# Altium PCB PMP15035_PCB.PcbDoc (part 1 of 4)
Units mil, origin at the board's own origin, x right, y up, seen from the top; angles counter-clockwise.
Board outline 5645 x 4585 mil, 8 copper layers (Top Layer, Signal Layer 1, Signal Layer 2, Signal Layer 3, Signal Layer 4, Signal Layer 5, Signal Layer 6, Bottom Layer), stack 60.9 mil thick; 335 components, 164 nets, 981 pads, 1349 vias.
Unrouted connection lines stored in the file: 46.
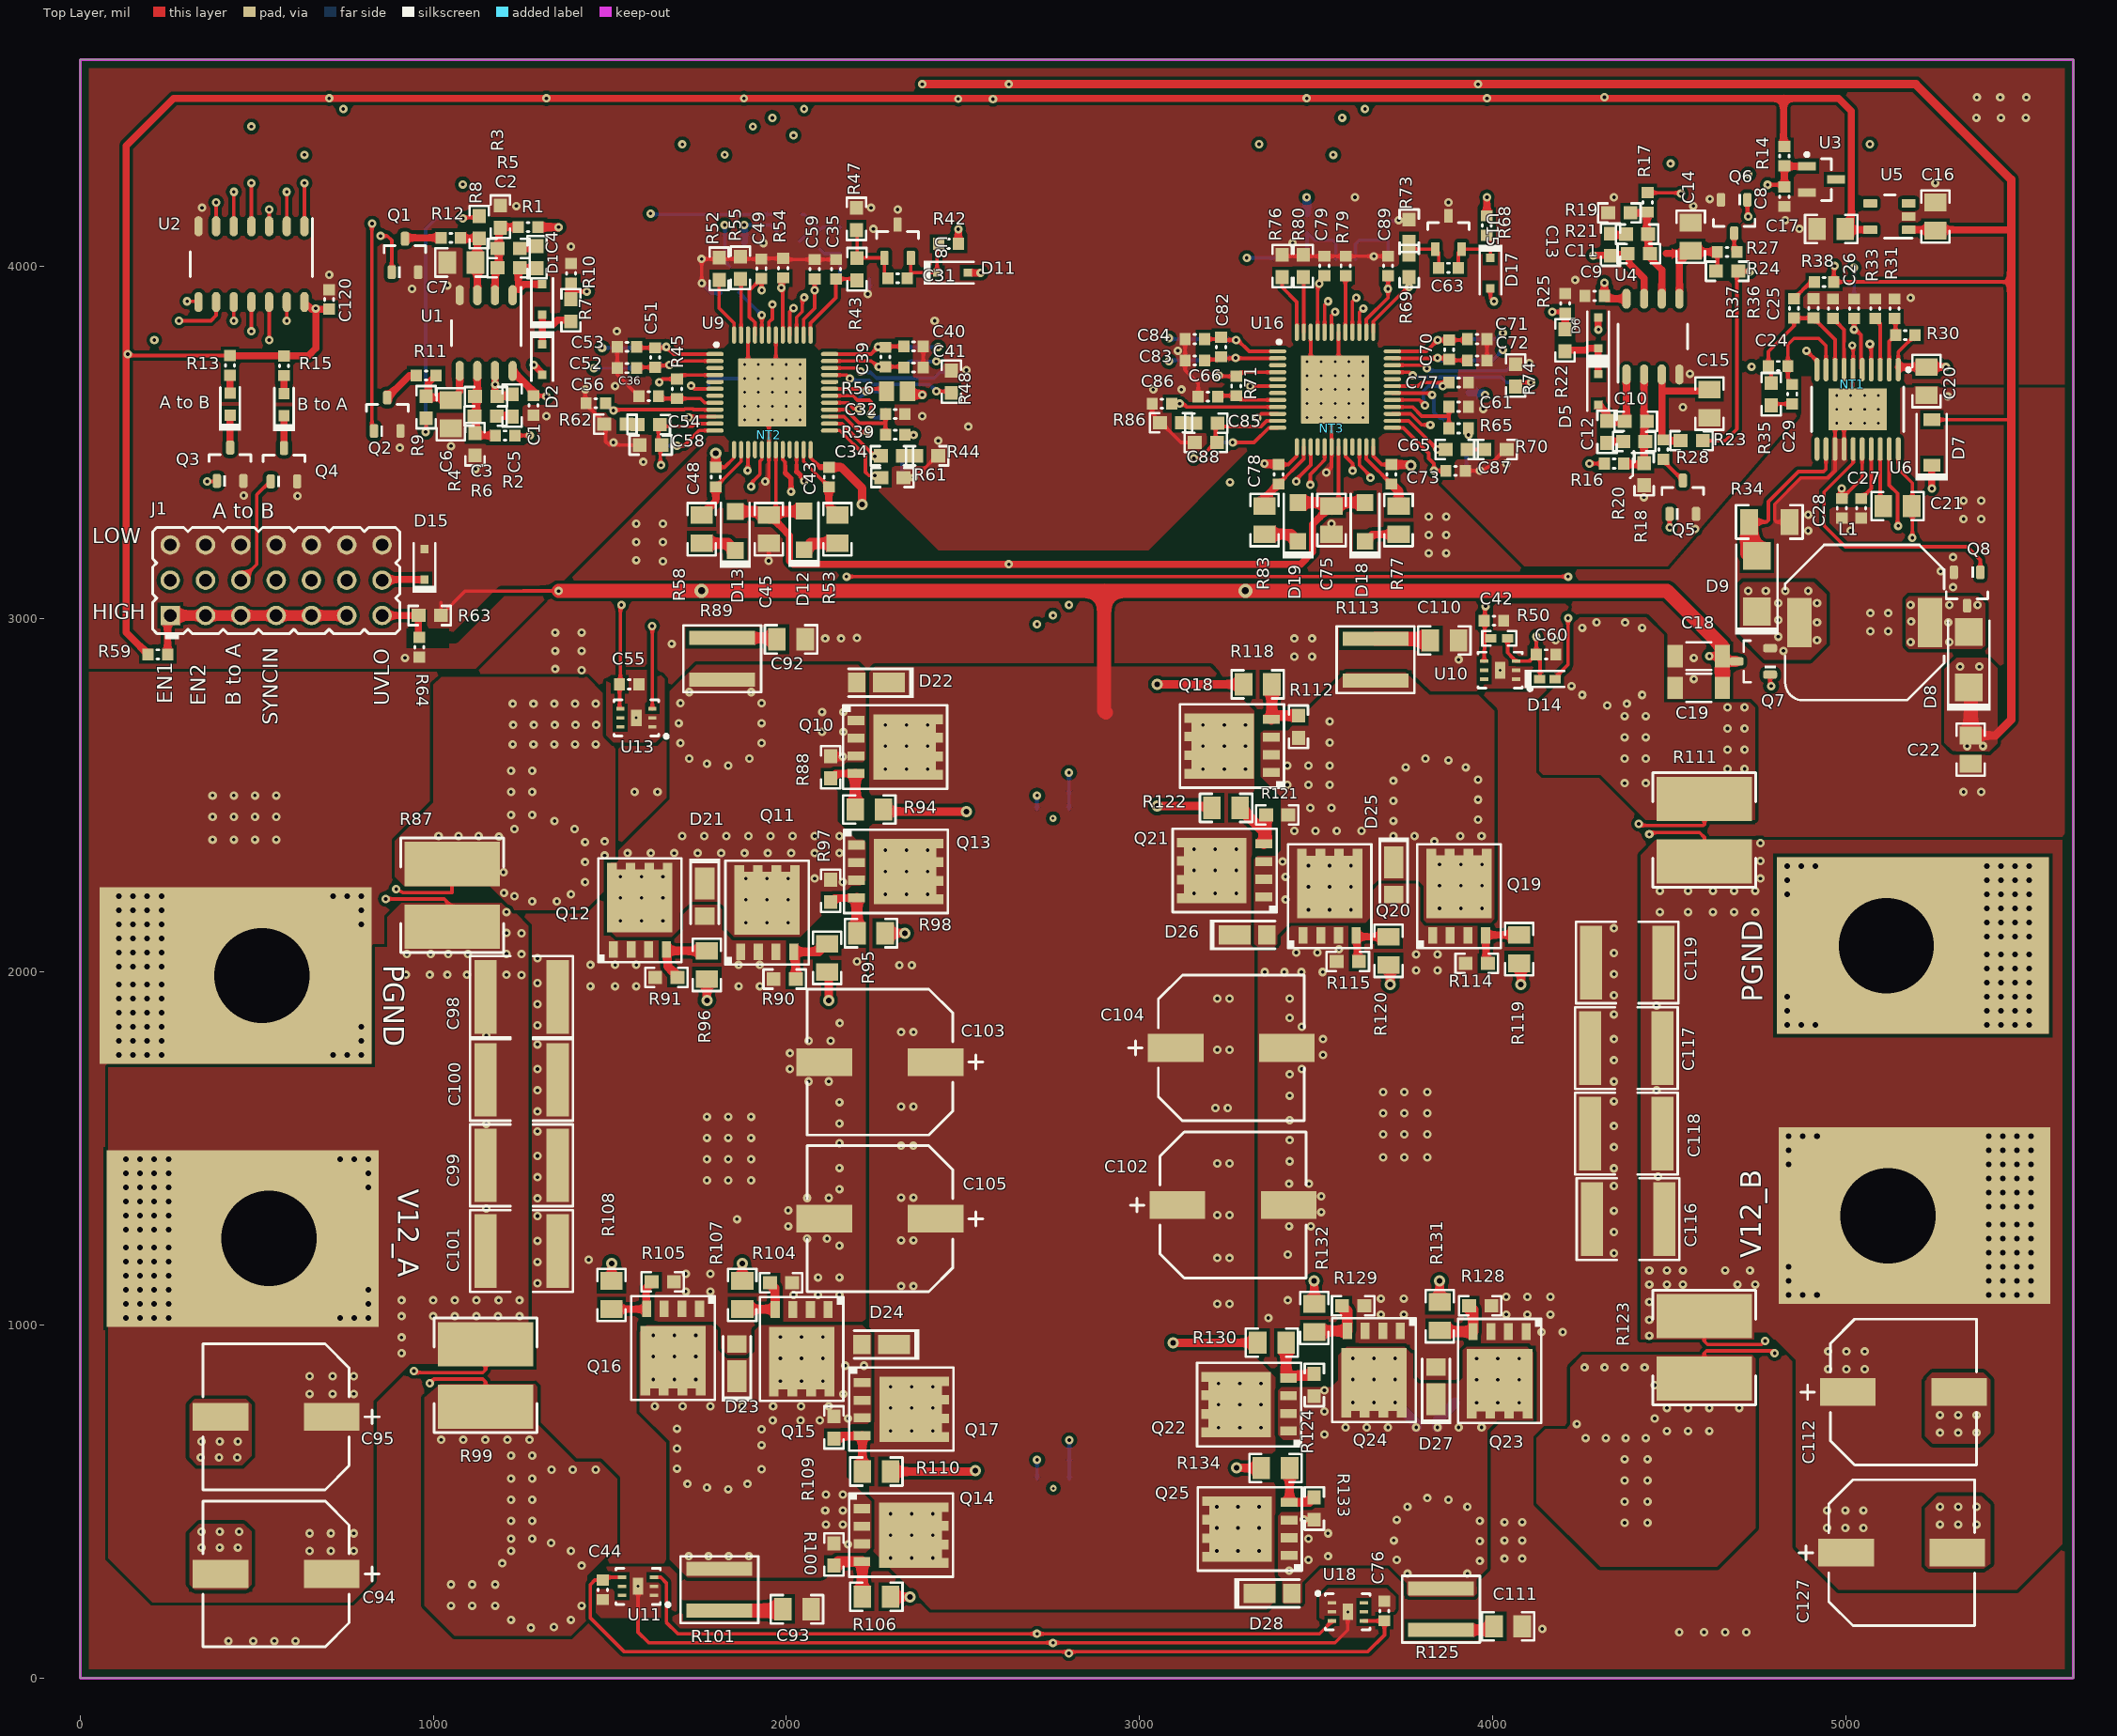
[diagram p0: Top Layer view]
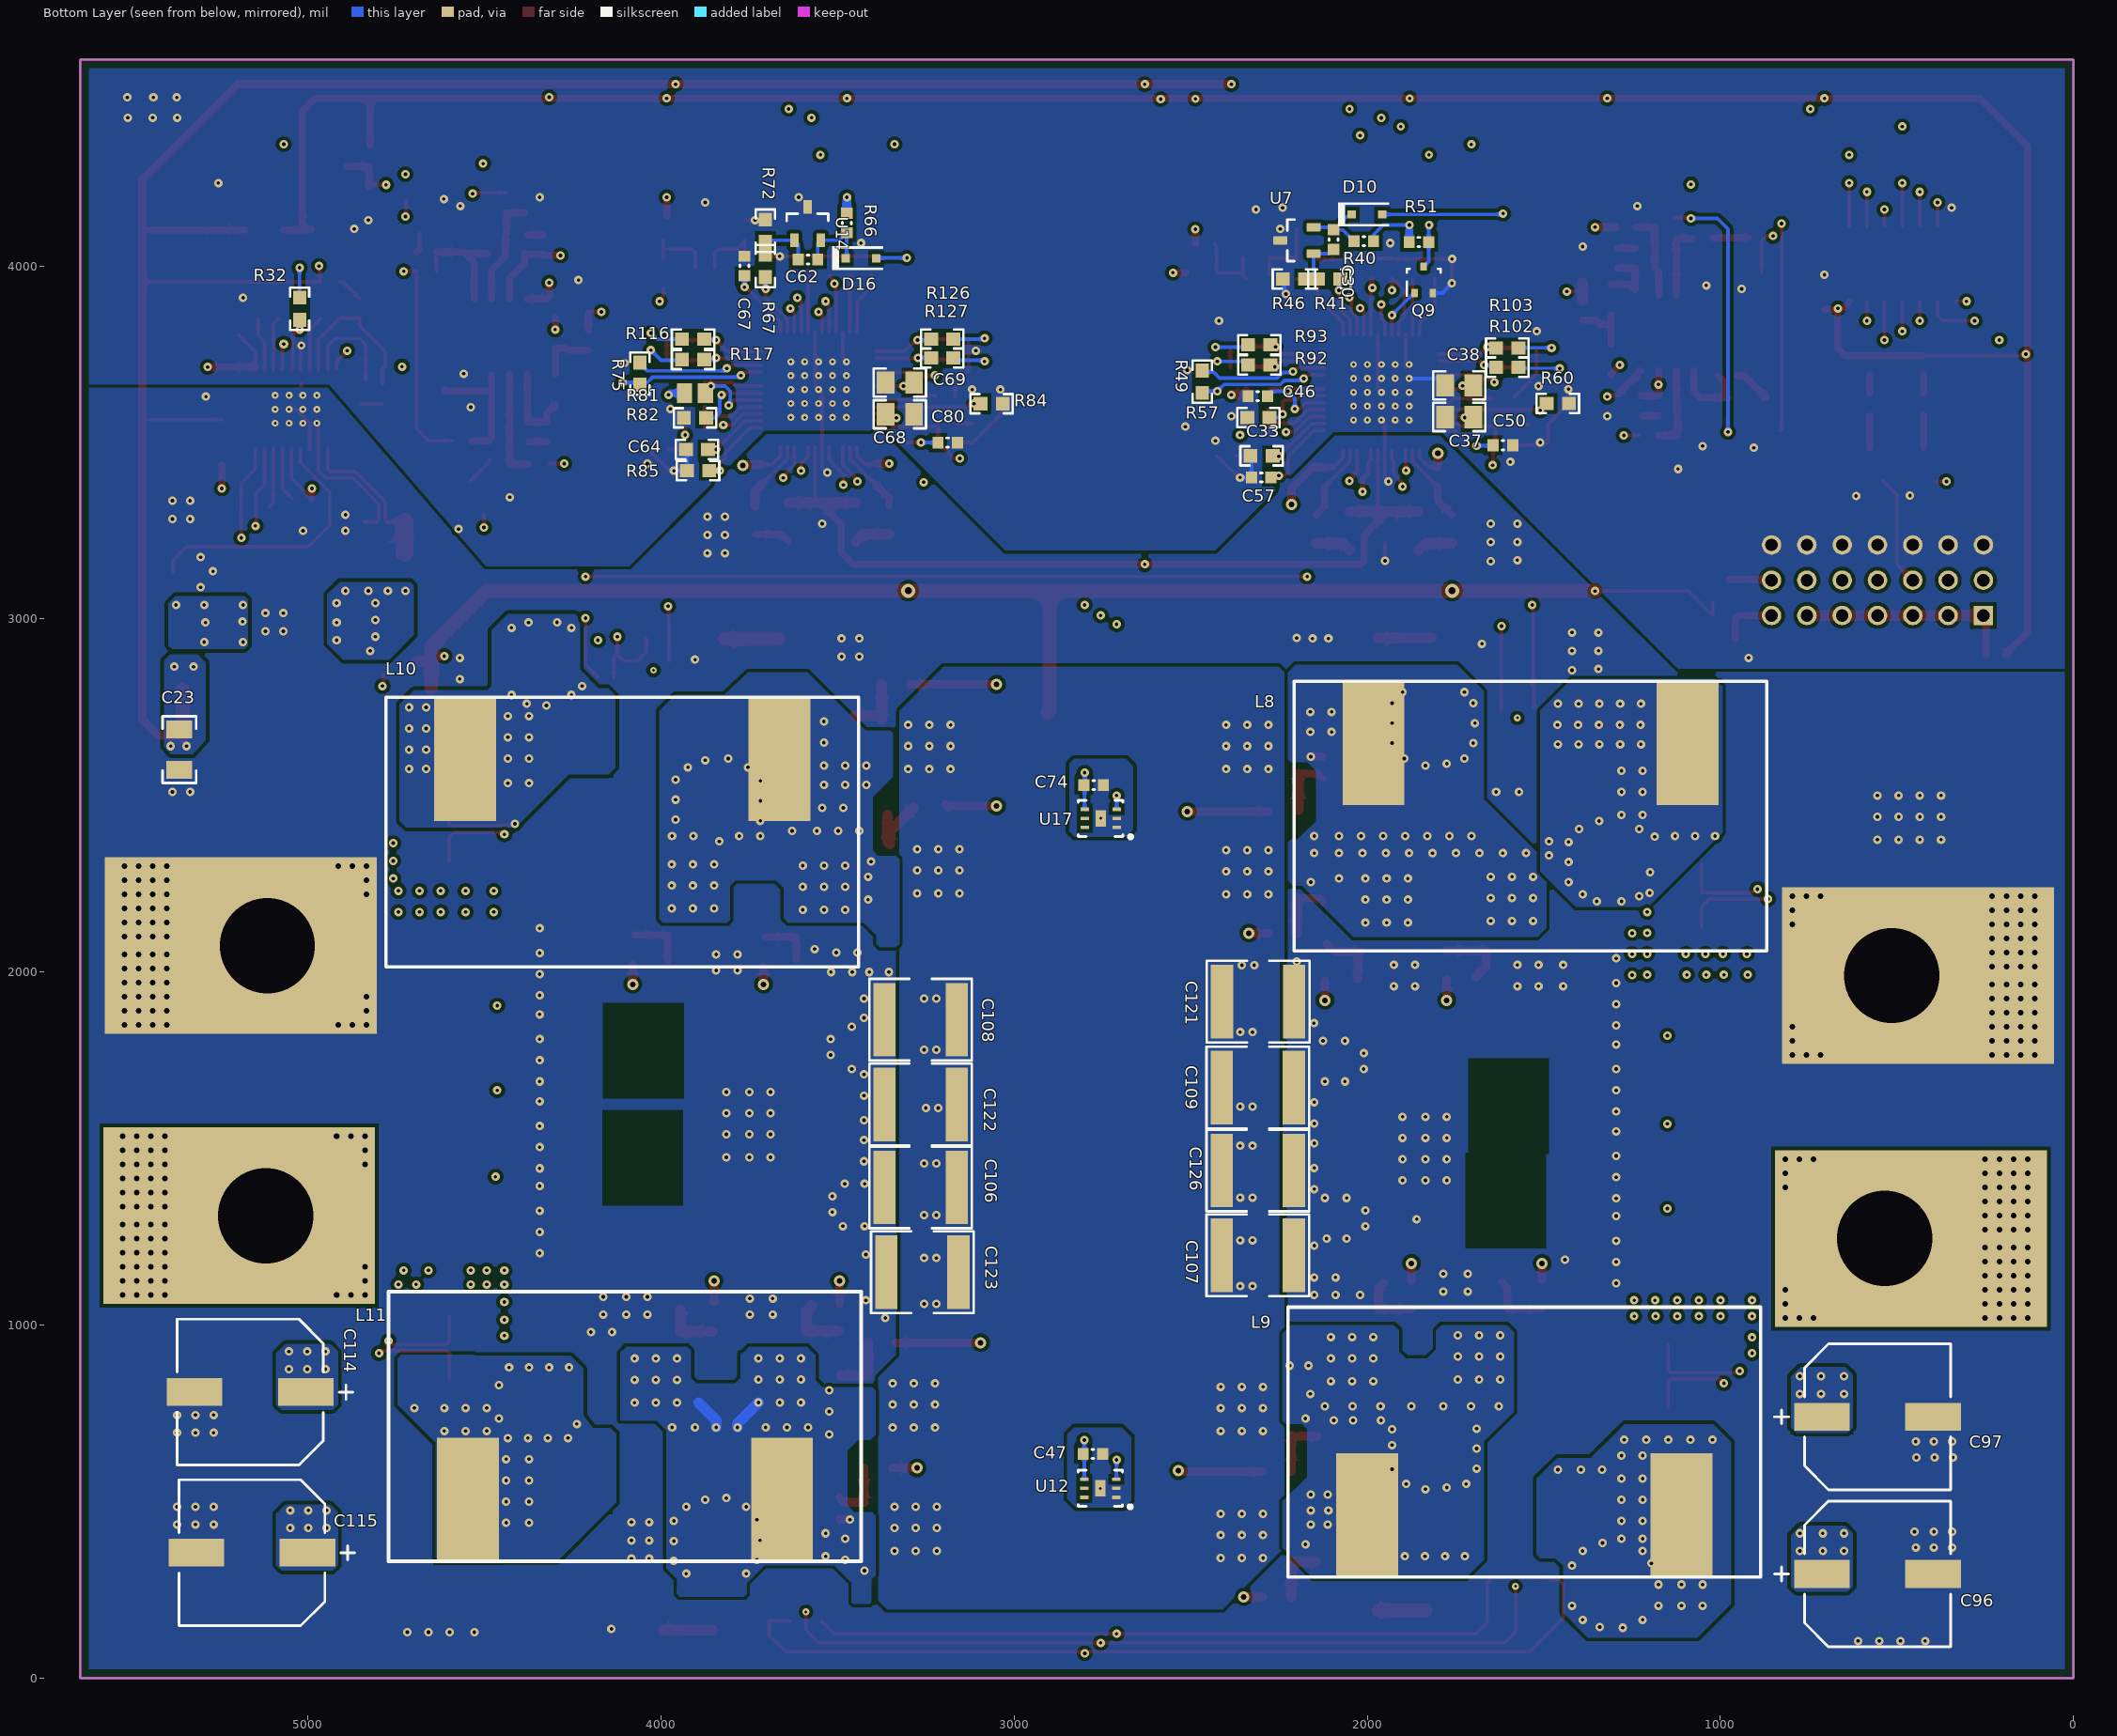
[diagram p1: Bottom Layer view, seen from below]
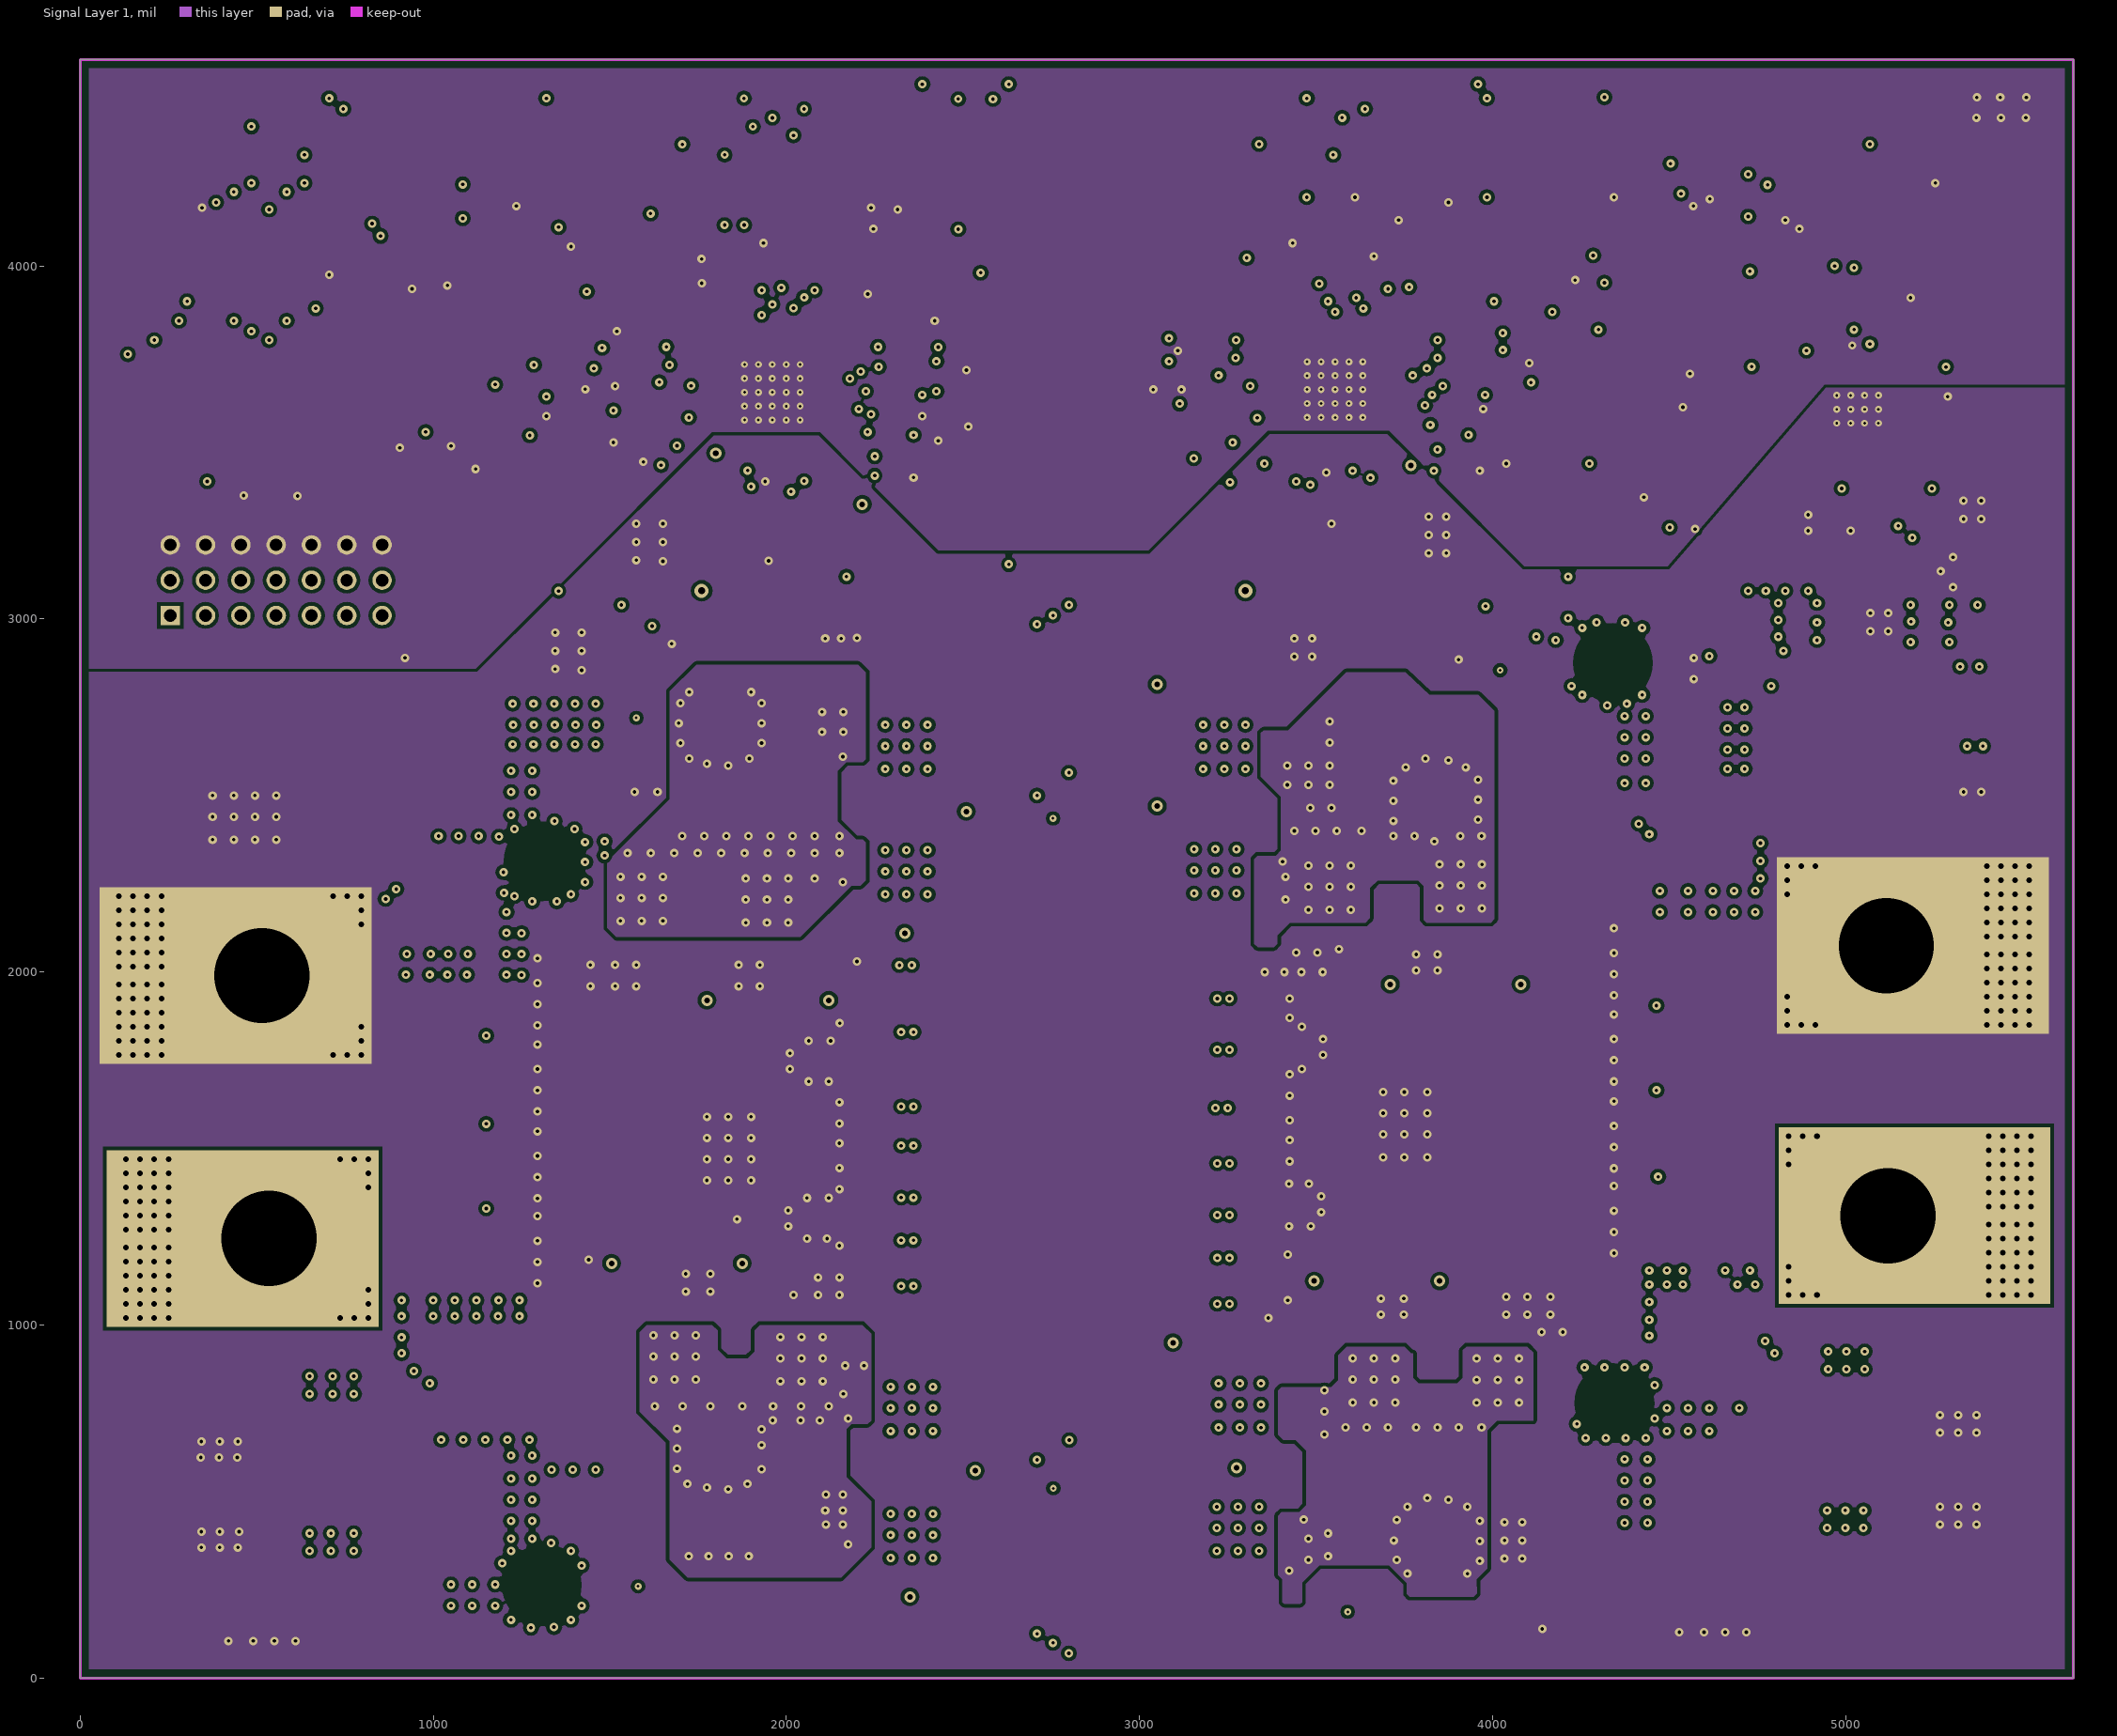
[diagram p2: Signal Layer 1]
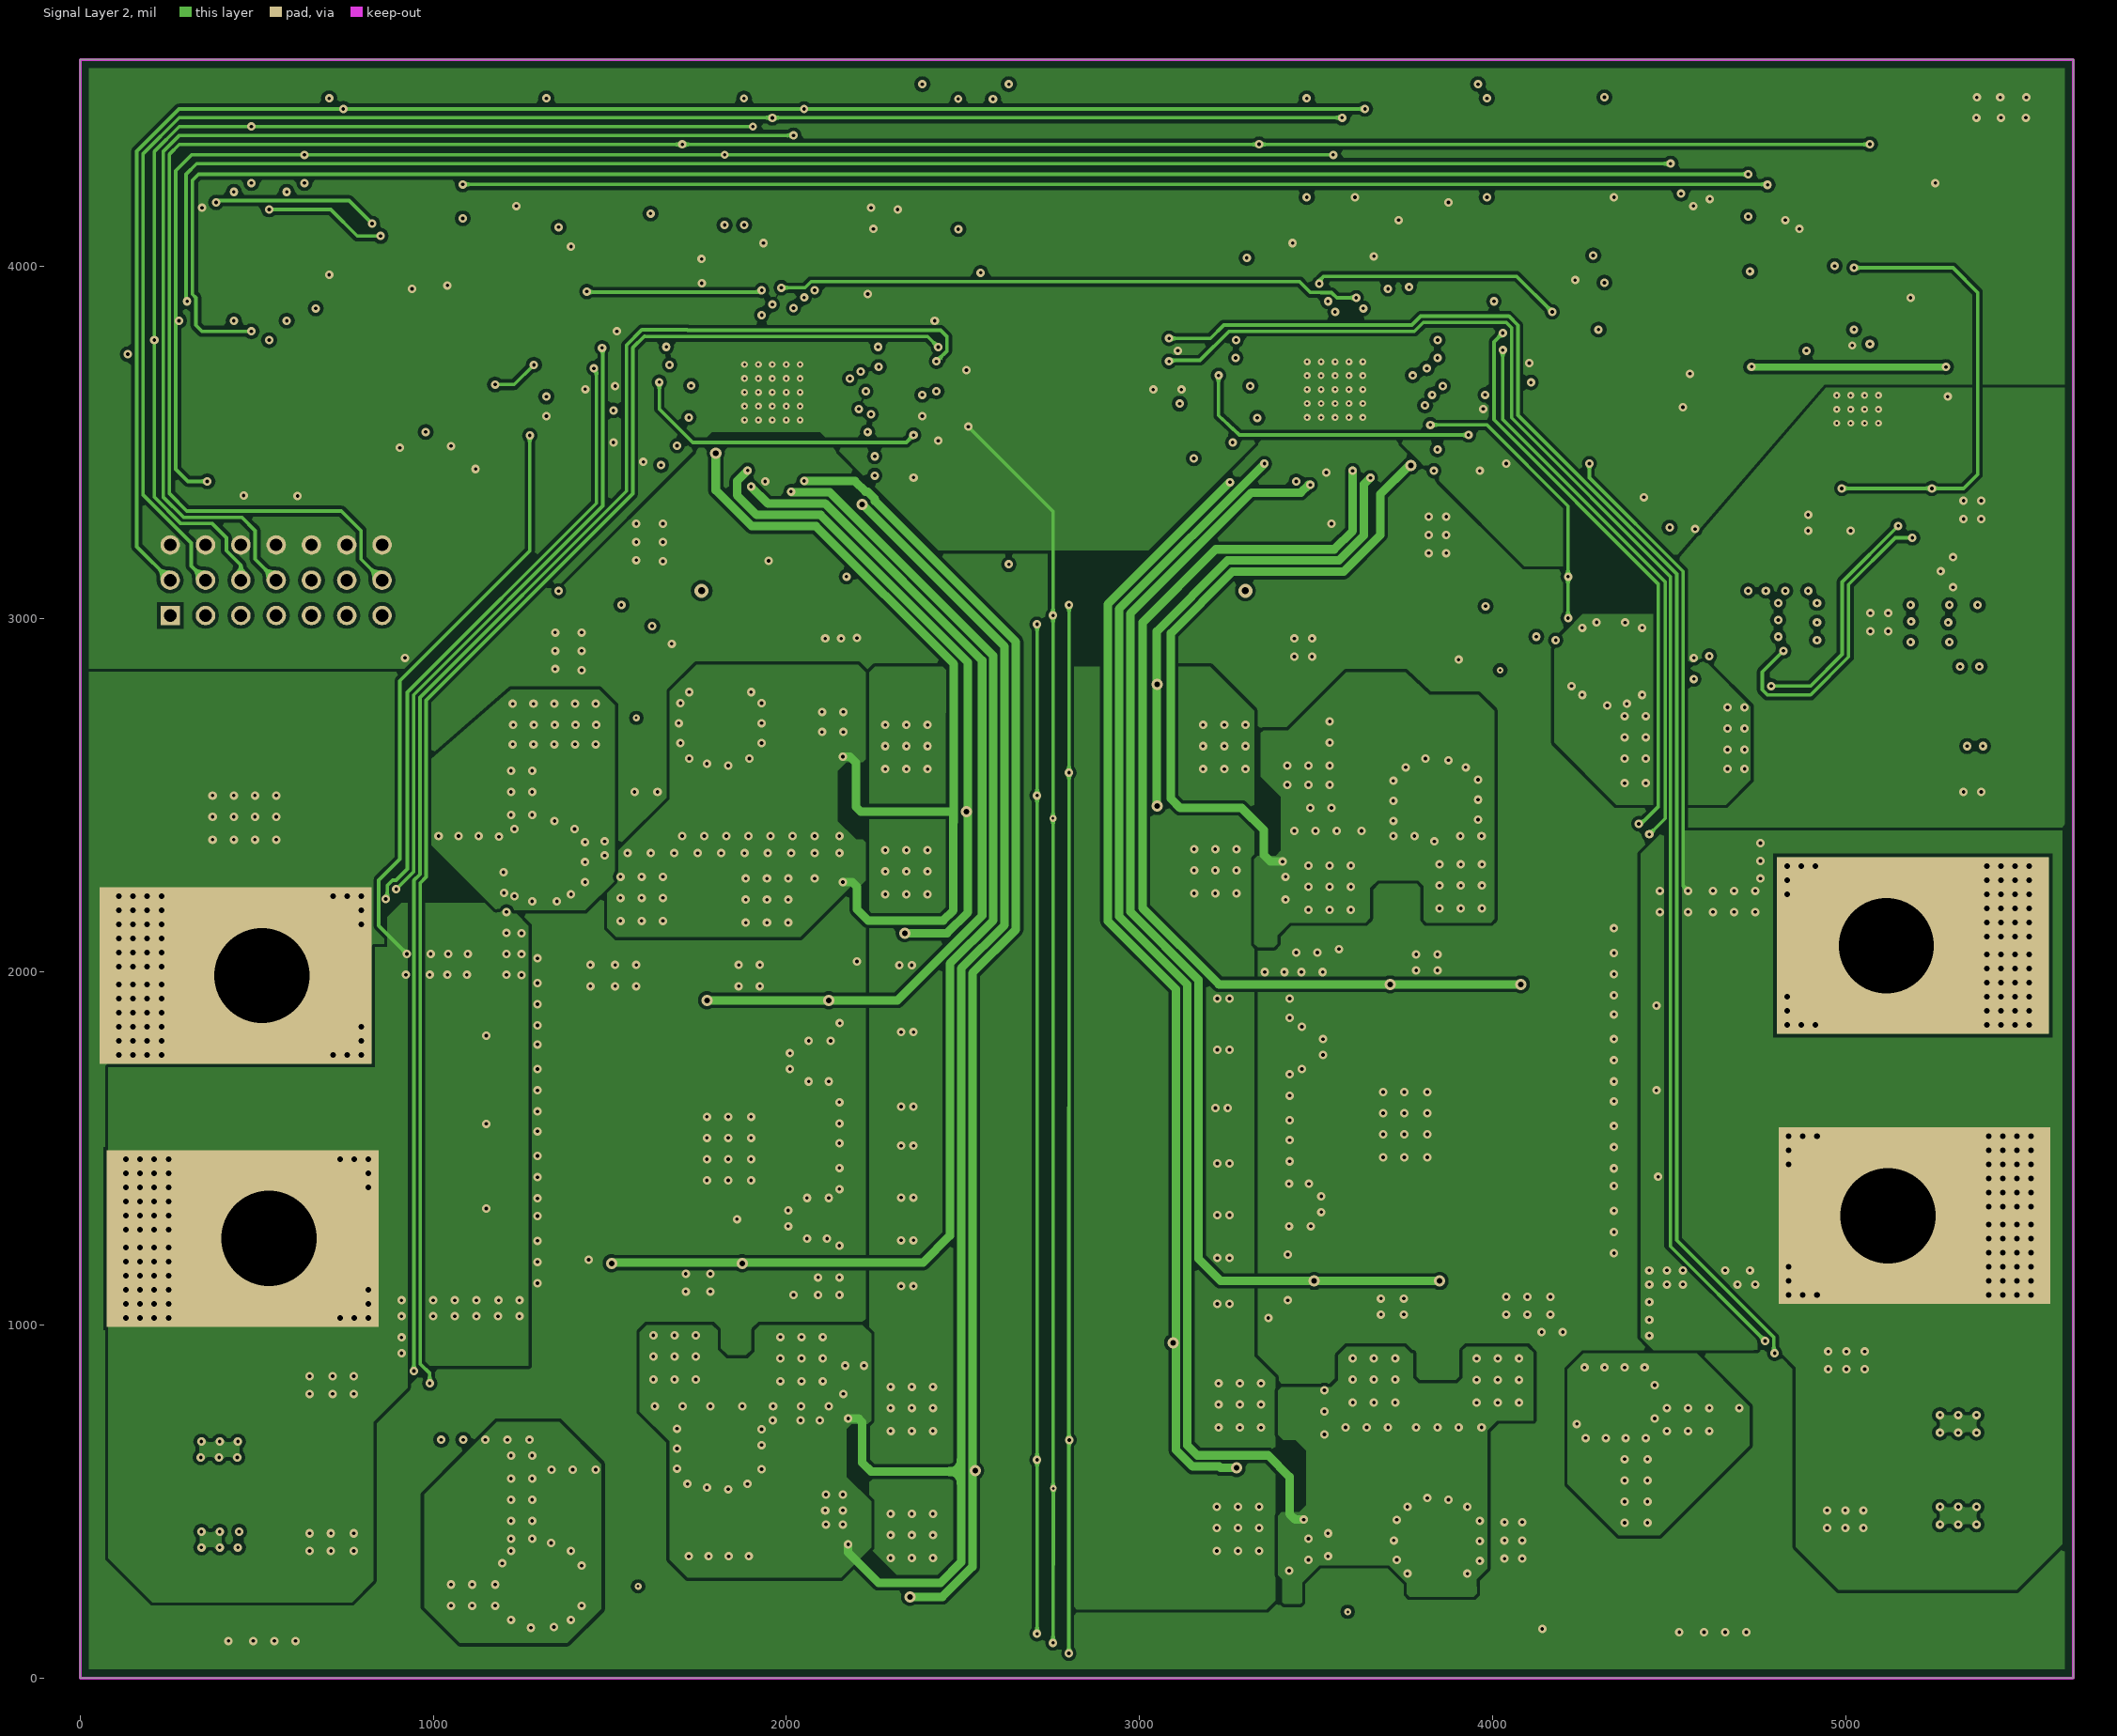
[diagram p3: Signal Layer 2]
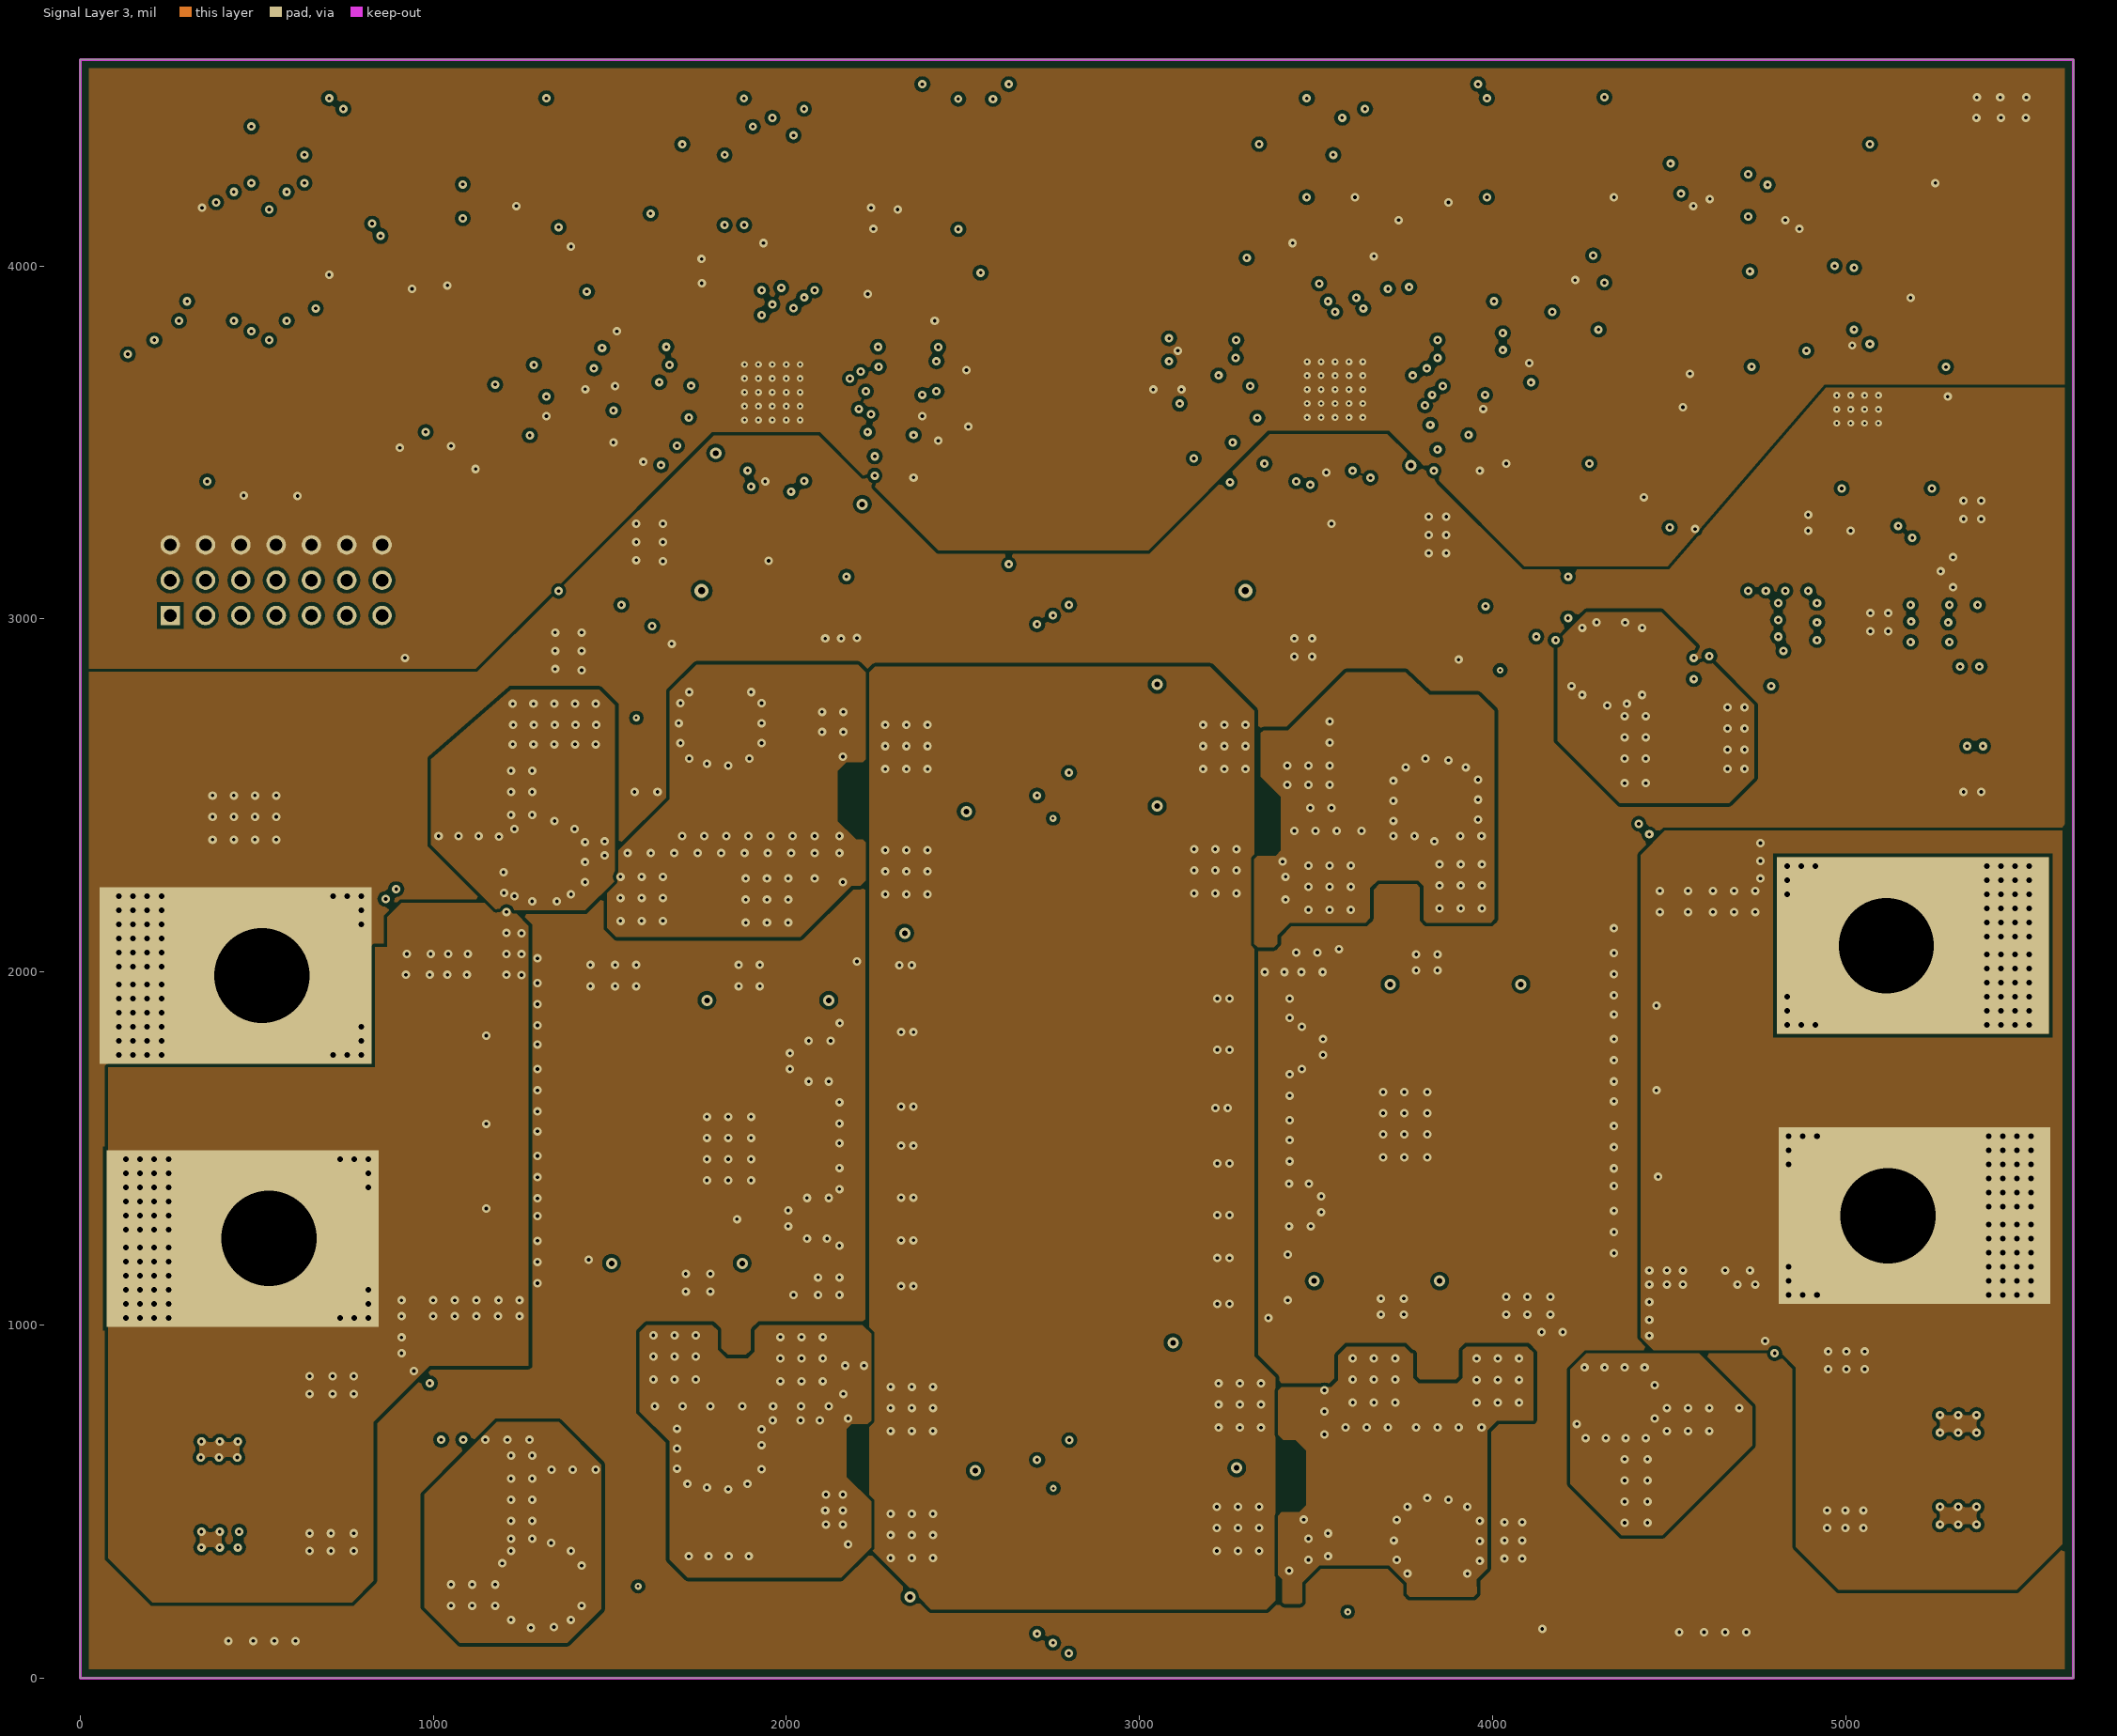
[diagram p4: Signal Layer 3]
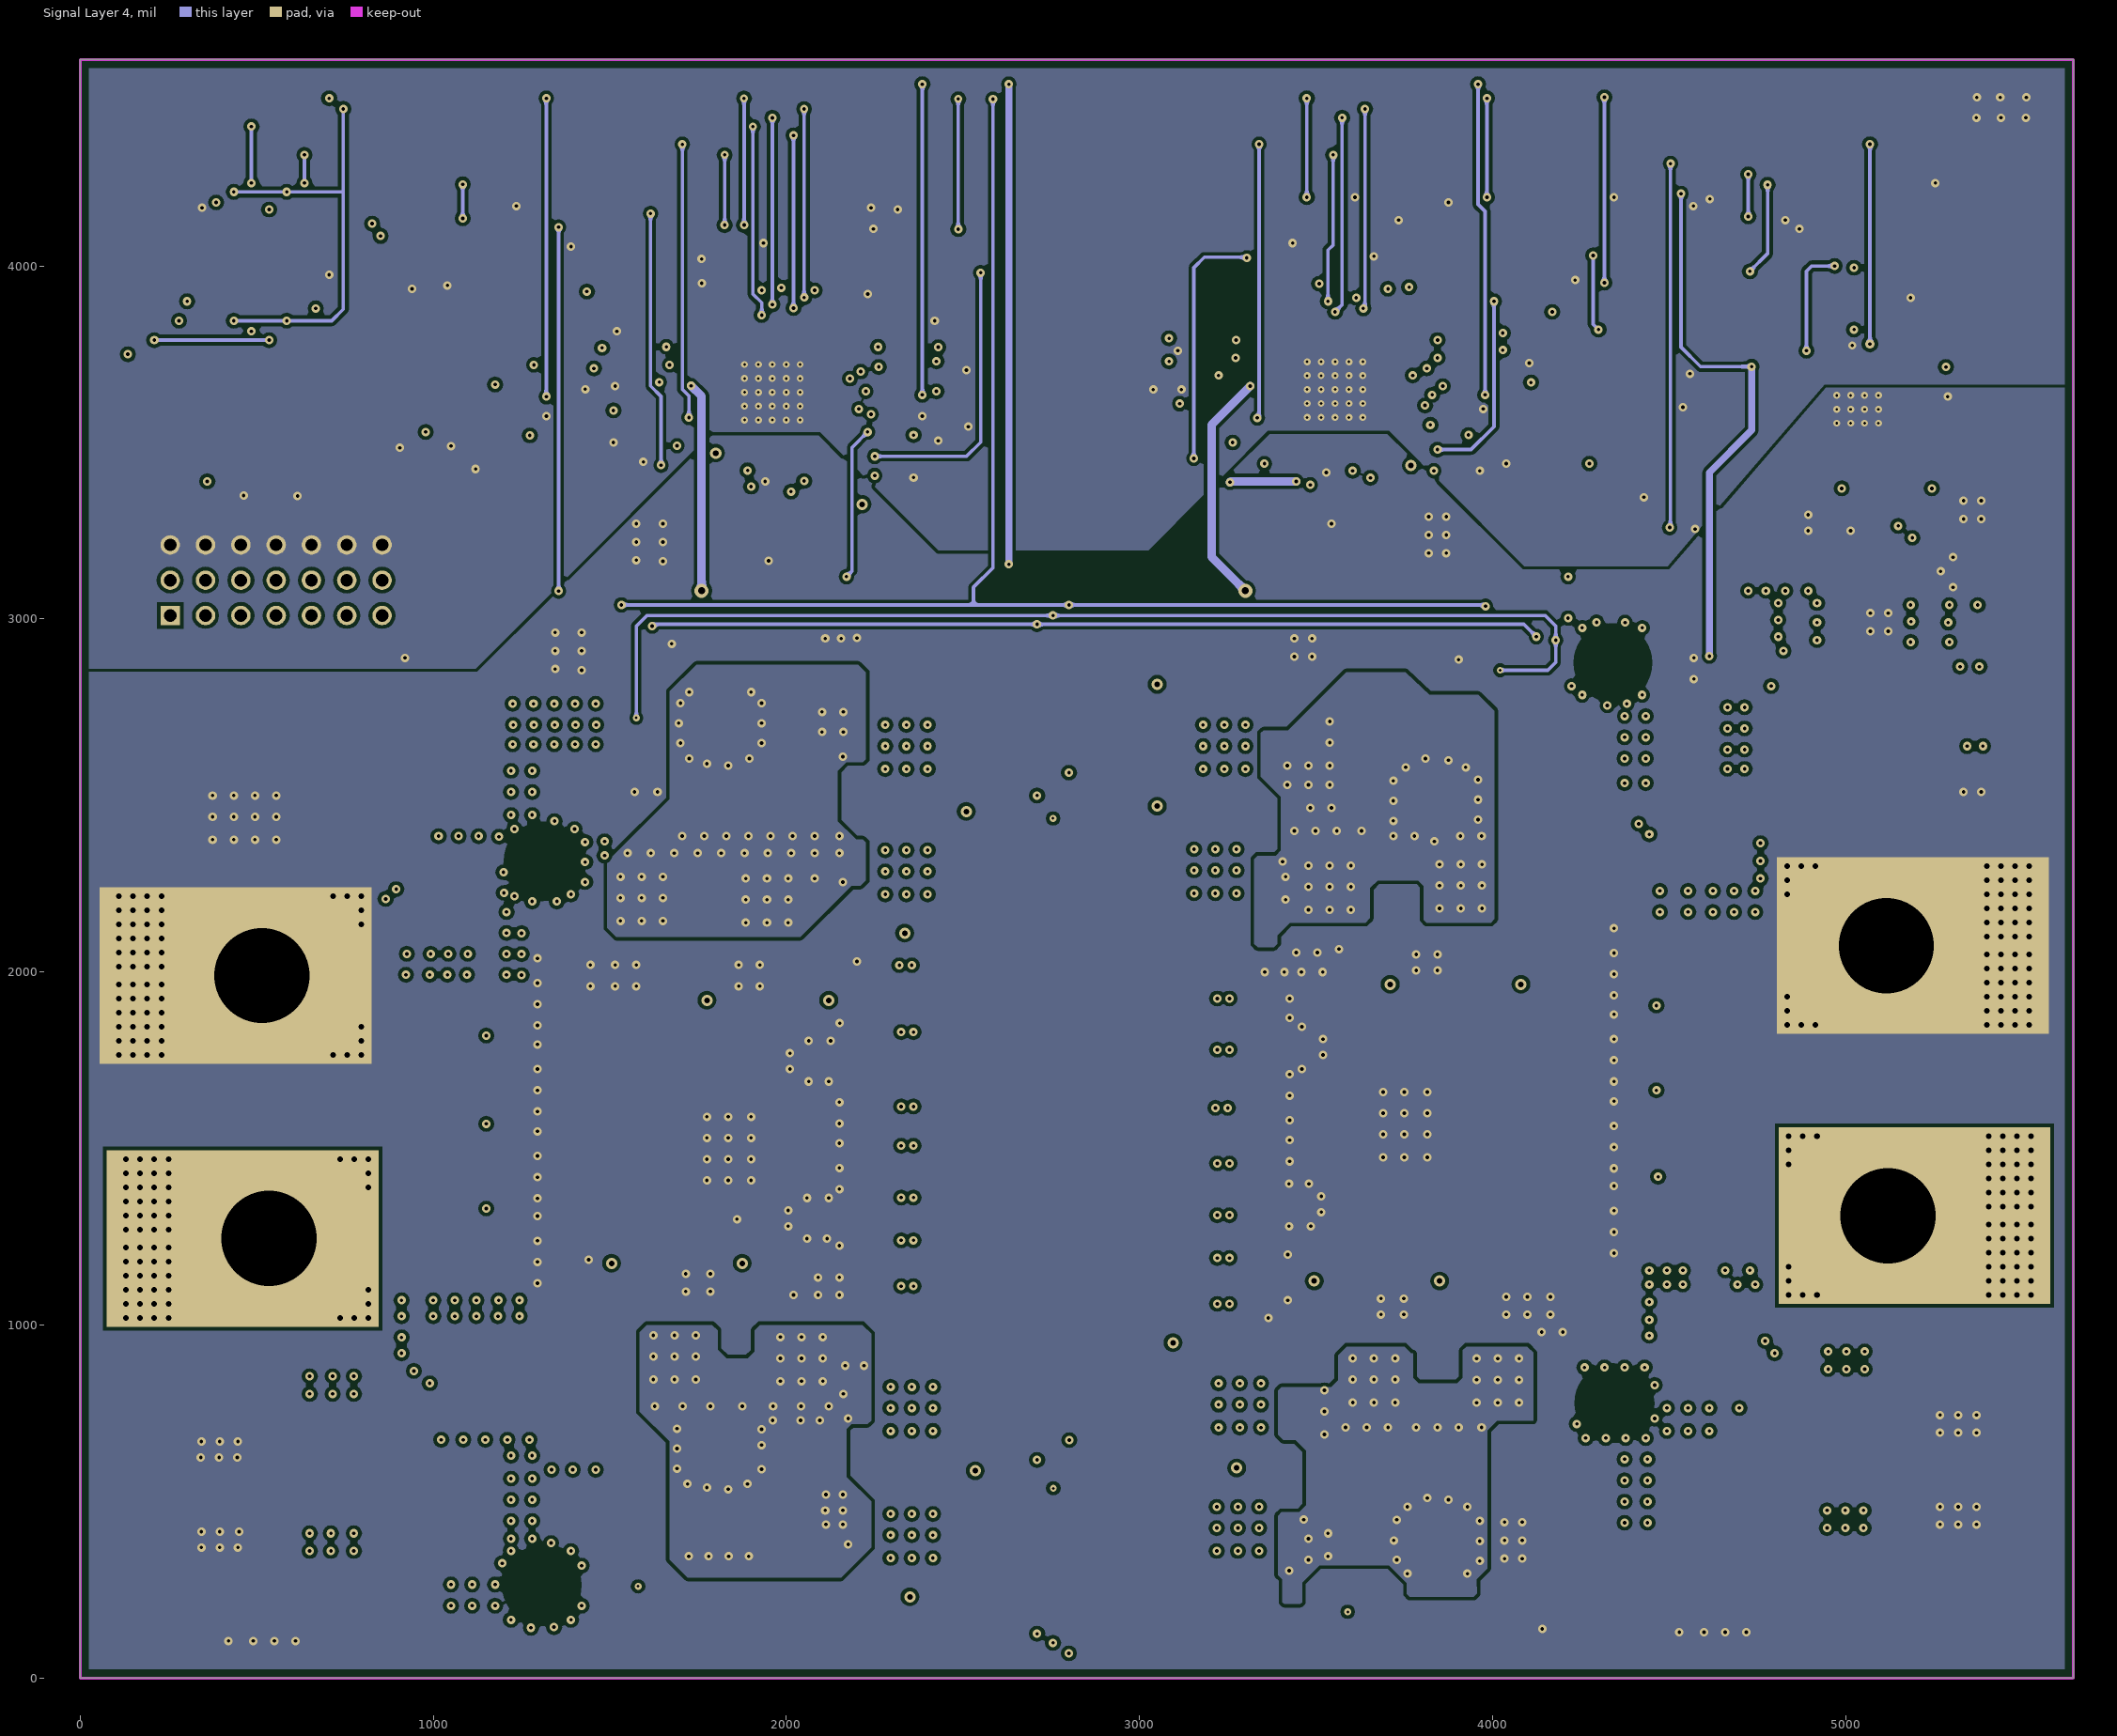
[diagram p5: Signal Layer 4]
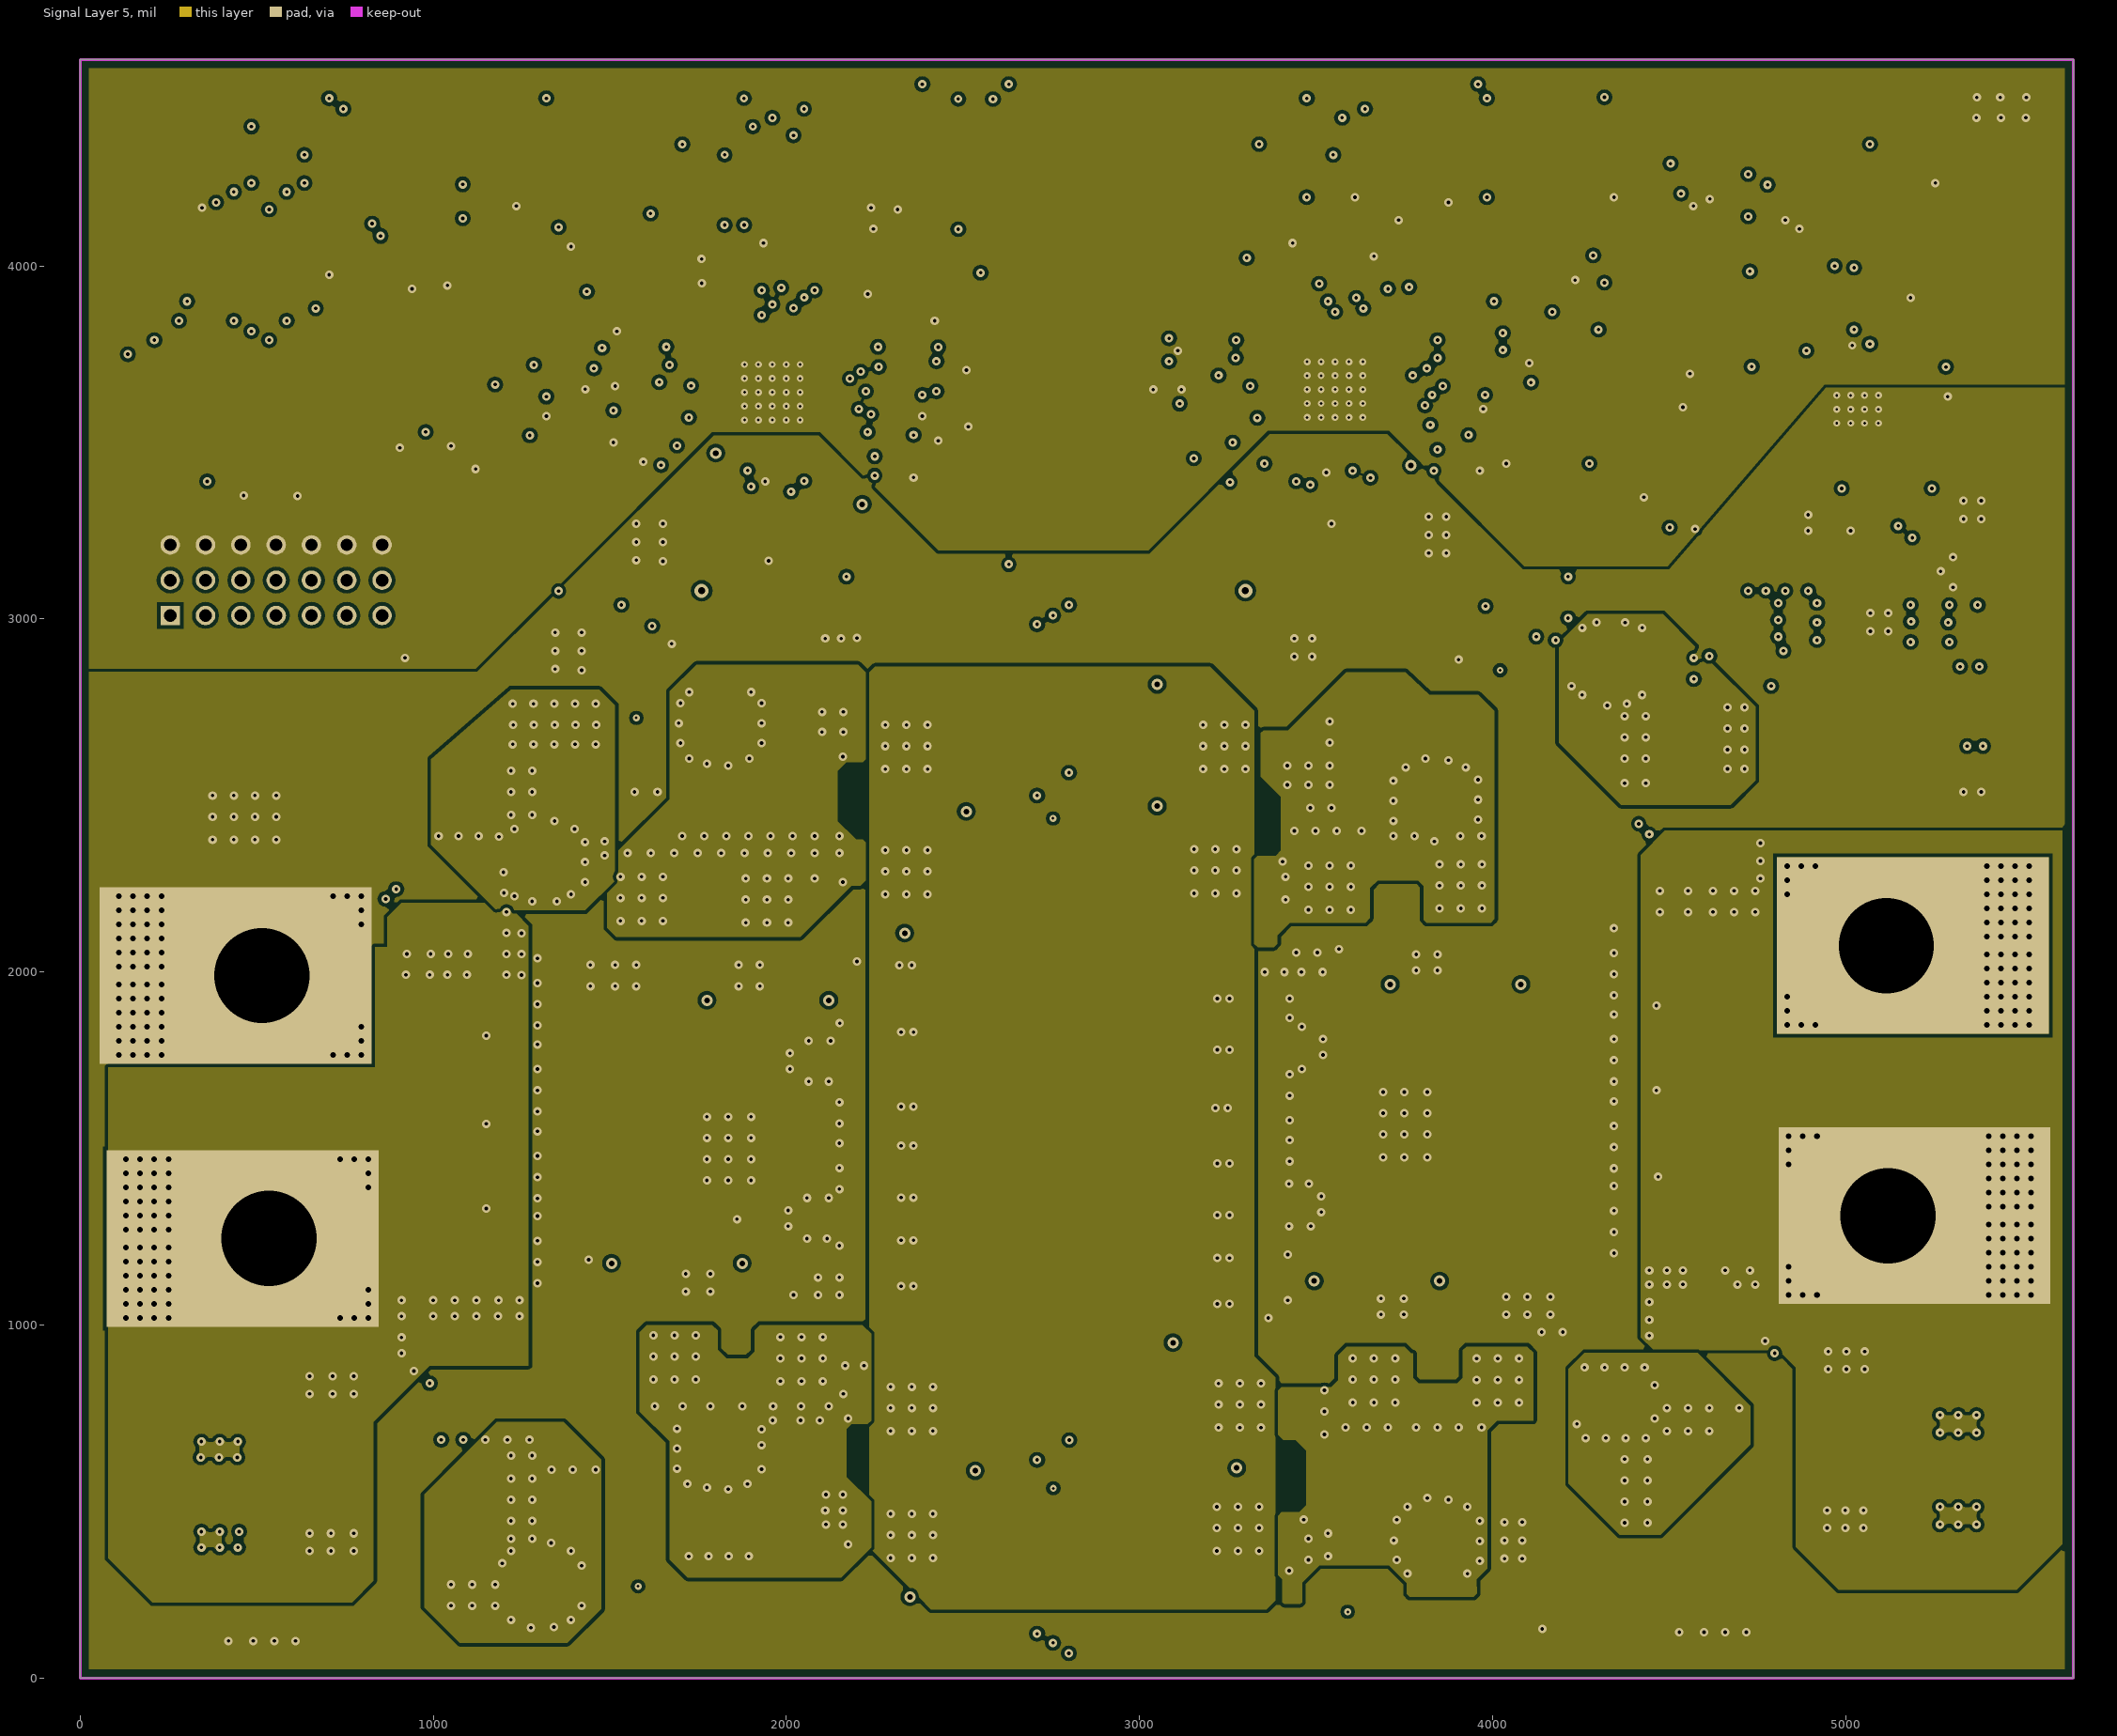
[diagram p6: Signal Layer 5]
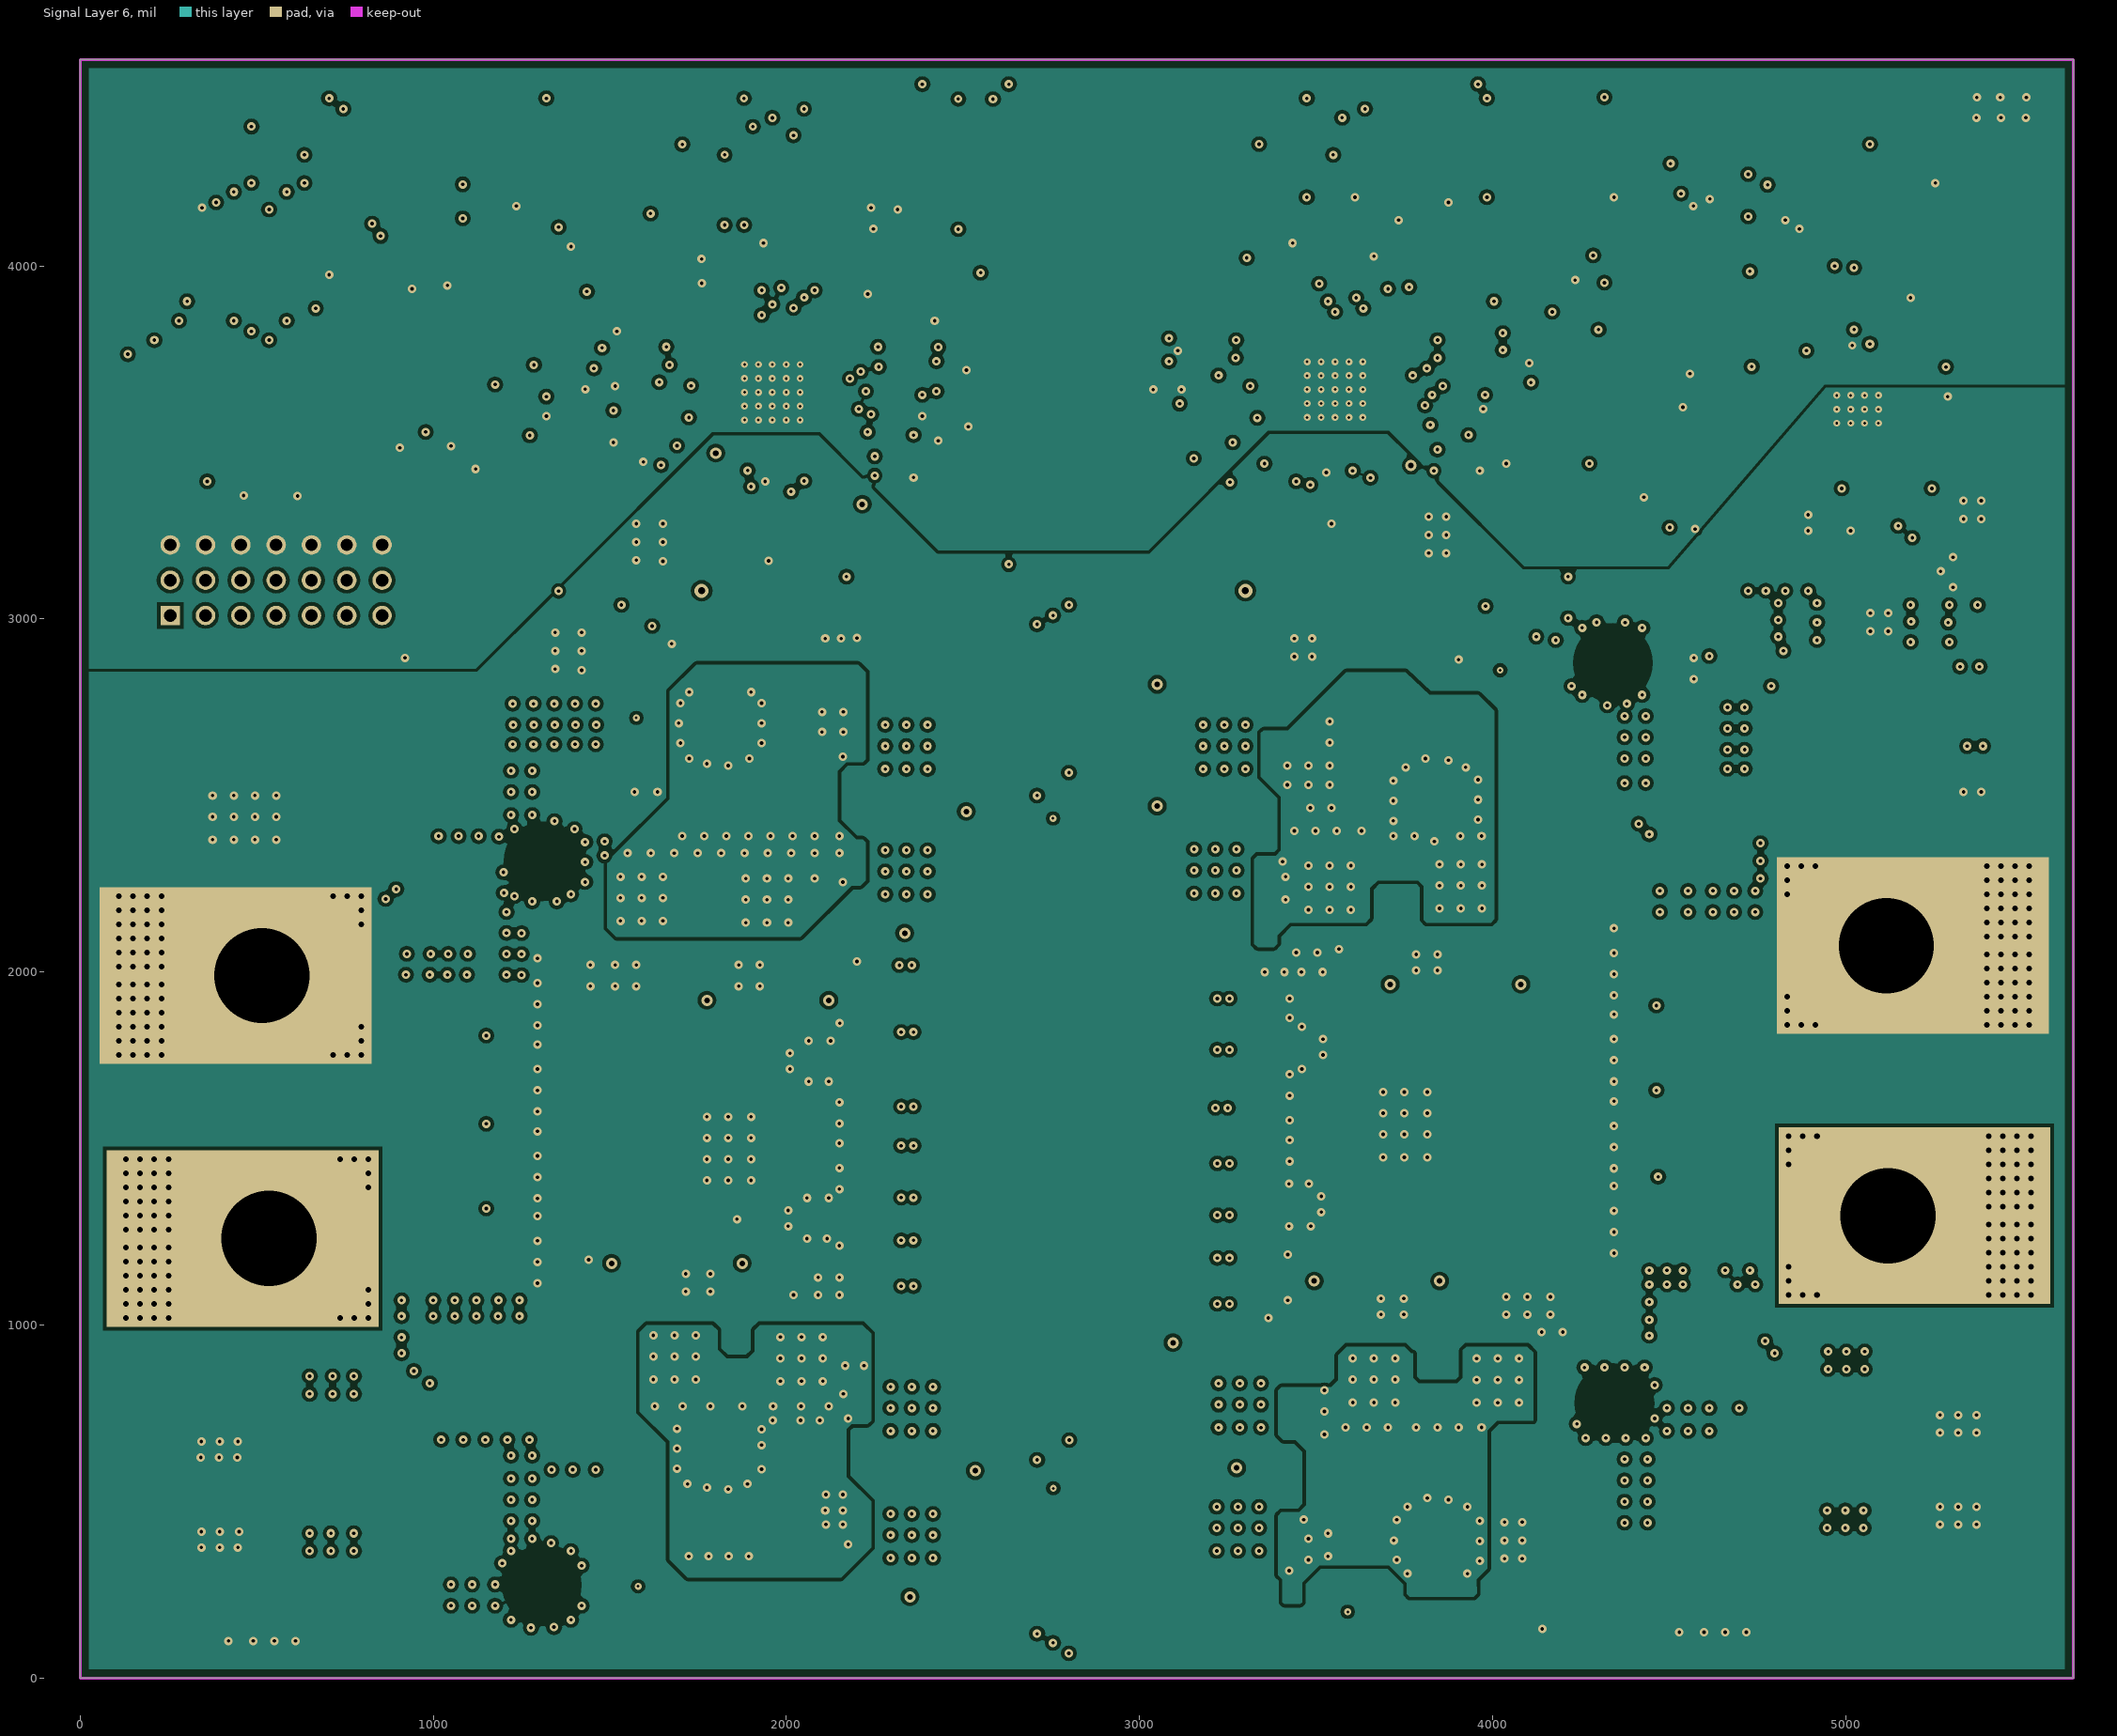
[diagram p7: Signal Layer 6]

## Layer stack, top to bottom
Top Solder: solder mask 0.4, Solder Resist, Dk 3.5
Top Layer: signal copper 2.8
Dielectric1: core 5.5, FR-4, Dk 4.8
Signal Layer 1: signal copper 2.8
Dielectric 2: dielectric 5.5, Dk 4.2
Signal Layer 2: signal copper 2.8
Dielectric 3: dielectric 5.5, Dk 4.2
Signal Layer 3: signal copper 2.8
Dielectric 4: dielectric 5.5, Dk 4.2
Signal Layer 4: signal copper 2.8
Dielectric 5: dielectric 5.5, Dk 4.2
Signal Layer 5: signal copper 2.8
Dielectric 6: dielectric 5.5, Dk 4.2
Signal Layer 6: signal copper 2.8
Dielectric 7: dielectric 5.5, Dk 4.2
Bottom Layer: signal copper 2.8
Bottom Solder: solder mask 0.4, Solder Resist, Dk 3.5

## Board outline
0,0 0,4585 5645,4585 5645,1.25 5643.75,0

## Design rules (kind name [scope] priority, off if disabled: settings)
AcuteAngle [All] p1: minimum=4.50000000000000E+0001 checktracksonly=FALSE
AssemblyTestPointUsage [All] p1: valid=2
BoardOutlineClearance BoardOutlineClearance_MountingHoles [OnCopper and InComponentClass('Mounting Holes')] p1: gap=40 ignorepadtopadclearanceinfootprint=FALSE
BoardOutlineClearance BoardOutlineClearance_Poly [OnCopper and IsPoly] p2: gap=25 ignorepadtopadclearanceinfootprint=FALSE
BoardOutlineClearance [OnCopper and Not InComponentClass('Logo') and not InComponentClass('FiducialMark') and not InRegion(1000,500,4000,800) and not InPoly] p3: gap=50 ignorepadtopadclearanceinfootprint=FALSE
Clearance Clearance_LUGs [HasFootprint('Panduit_CXS70-14-C') vs OnLayer('Keep-Out Layer')] p1: gap=0 ignorepadtopadclearanceinfootprint=FALSE
Clearance Clearance_Keepouts [((IsTrack Or IsArc) And Not InPoly) And IsFree and IsKeepOut vs ((IsTrack Or IsArc) And Not InPoly) And IsFree and IsKeepOut] p2: gap=0 ignorepadtopadclearanceinfootprint=FALSE
Clearance Clearance_Poly [InPolygon] p3: gap=10 ignorepadtopadclearanceinfootprint=FALSE
Clearance Clearance_FiducialMark [IsKeepOut and InComponentClass('FiducialMark') vs IsPad and InComponentClass('FiducialMark')] p4: gap=0 ignorepadtopadclearanceinfootprint=FALSE
Clearance [All] p5: gap=7.87 ignorepadtopadclearanceinfootprint=FALSE except(0: Arc-Hole Track-Hole SMDPad-Hole THPad-Hole Via-Hole Fill-Hole Poly-Hole Region-Hole Text-Hole)
ComponentClearance ComponentClearance_6 [InComponent('U6') vs InComponent('NT1')] p1: gap=0 collisioncheckmode=3 verticalgap=0 showdistances=FALSE
ComponentClearance ComponentClearance_5 [InComponent('NT2') vs InComponent('U9')] p2: gap=0 collisioncheckmode=3 verticalgap=0 showdistances=FALSE
ComponentClearance ComponentClearance_4 [InComponent('U16') vs InComponent('NT3')] p3: gap=0 collisioncheckmode=3 verticalgap=0 showdistances=FALSE
ComponentClearance ComponentClearance_3 [HasFootprint('PCBComponent_1') vs HasFootprint('ERU33')] p4: gap=0 collisioncheckmode=3 verticalgap=0 showdistances=FALSE
ComponentClearance ComponentClearance_2 [HasFootprint('PCBComponent_1') vs HasFootprint('SER2915H')] p5: gap=0 collisioncheckmode=3 verticalgap=0 showdistances=FALSE
ComponentClearance ComponentClearance_1 [HasFootprint('SER2915H') vs HasFootprint('ERU33')] p6: gap=0 collisioncheckmode=3 verticalgap=0 showdistances=FALSE
ComponentClearance ComponentClearance_Lug [HasFootprint('Panduit_CXS70-14-C') vs HasFootprint('Johnson_108-0740-001')] p7: gap=0 collisioncheckmode=3 verticalgap=0 showdistances=FALSE
ComponentClearance ComponentClearance_MountingHoles_FiducialMarks [InComponentClass('Mounting Holes') vs InComponentClass('FiducialMark')] p8: gap=50 collisioncheckmode=3 verticalgap=10 showdistances=FALSE
ComponentClearance ComponentClearance_Shunt [InComponentClass('Header') vs InComponentClass('Shunt')] p9: gap=0 collisioncheckmode=3 verticalgap=0 showdistances=FALSE
ComponentClearance ComponentClearance_Logo [InComponentClass('Logo')] p10: gap=50 collisioncheckmode=3 verticalgap=10 showdistances=FALSE
ComponentClearance ComponentClearance_ScrewToNut [(HasFootprint('NY PMS 440 0025 PH')) vs (HasFootprint('Keystone_1902C'))] p11: gap=5 collisioncheckmode=3 verticalgap=10 showdistances=FALSE
ComponentClearance ComponentClearance_MountingHoles [InComponentClass('Mounting Holes')] p12: gap=250 collisioncheckmode=3 verticalgap=100000 showdistances=FALSE
ComponentClearance ComponentClearance_SmallPassives [HasFootprint('0201*') or HasFootprint('0402*') or HasFootprint('0508') or HasFootprint('0603*') or HasFootprint('0612') or HasFootprint('0805*') or HasFootprint('0815*') or HasFootprint('0830*') or HasFootprint('1206*') or HasFootprint('1210*') or HasFootprint('1808*') or HasFootprint('1812*') or HasFootprint('1825*') or HasFootprint('2010*') or HasFootprint('2220*') or HasFootprint('2225*') or HasFootprint('2512*') or HasFootprint('2728*') or HasFootprint('3518*') vs HasFootprint('0201*') or HasFootprint('0402*') or HasFootprint('0508') or HasFootprint('0603*') or HasFootprint('0612') or HasFootprint('0805*') or HasFootprint('0815*') or HasFootprint('0830*') or HasFootprint('1206*') or HasFootprint('1210*') or HasFootprint('1808*') or HasFootprint('1812*') or HasFootprint('1825*') or HasFootprint('2010*') or HasFootprint('2220*') or HasFootprint('2225*') or HasFootprint('2512*') or HasFootprint('2728*') or HasFootprint('3518*')] p13: gap=14.96 collisioncheckmode=3 verticalgap=10 showdistances=FALSE
ComponentClearance ComponentClearance_THtoSMT [IsThruComponent vs IsSMTComponent] p14: gap=40 collisioncheckmode=3 verticalgap=30 showdistances=FALSE
ComponentClearance ComponentClearance_THtoTH [IsThruComponent vs IsThruComponent] p15: gap=30 collisioncheckmode=3 verticalgap=30 showdistances=FALSE
ComponentClearance [All] p16: gap=30 collisioncheckmode=3 verticalgap=10 showdistances=FALSE
DiffPairsRouting [All] p1: maxlimit=100 minlimit=10 mostfreqgap=10 toplayer_minwidth=15 toplayer_maxwidth=15 toplayer_prefwidth=15 midlayer1_minwidth=15 midlayer1_maxwidth=15 midlayer1_prefwidth=15 midlayer2_minwidth=15 midlayer2_maxwidth=15 midlayer2_prefwidth=15 midlayer3_minwidth=15 midlayer3_maxwidth=15 midlayer3_prefwidth=15 midlayer4_minwidth=15 midlayer4_maxwidth=15 midlayer4_prefwidth=15 midlayer5_minwidth=15 midlayer5_maxwidth=15 midlayer5_prefwidth=15 midlayer6_minwidth=15 midlayer6_maxwidth=15 midlayer6_prefwidth=15 bottomlayer_minwidth=15 bottomlayer_maxwidth=15 bottomlayer_prefwidth=15 maxuncoupledlength=1000
FabricationTestPointUsage TestPointUsage [All] p1: valid=2 allowmultiple=FALSE
FabricationTestpoint Testpoint [All] p1: side=3 testpointundercomponent=TRUE minsize=40 maxsize=100 preferedsize=60 minholesize=0 maxholesize=40 preferedholesize=32 testpointgrid=1 allowsidetop=TRUE allowsidebottom=TRUE usegrid=TRUE gridtolerance=0.01
FanoutControl Fanout_LCC [IsLCC] p1: bgadir=Out bgaviamode=Centered fanoutstyle=Auto fanoutdirection=Alternating viagrid=1 // Fanout_LCC (Default Rule)
FanoutControl Fanout_BGA [IsBGA] p2: bgadir=Out bgaviamode=Centered fanoutstyle=Auto fanoutdirection=Alternating viagrid=1 // Fanout_BGA (Default Rule)
FanoutControl Fanout_Default [All] p4: bgadir=Out bgaviamode=Centered fanoutstyle=Auto fanoutdirection=Alternating viagrid=1 // Fanout_Default (Default Rule)
FanoutControl Fanout_Small [(CompPinCount < 5)] p5: bgadir=Out bgaviamode=Centered fanoutstyle=Auto fanoutdirection=OutThenIn viagrid=1 // Fanout_Small (Default Rule)
HoleSize [All] p1: absolutevalues=TRUE maxlimit=280 minlimit=7.87 maxpercent=80.000 minpercent=20.000
MinimumAnnularRing MinimumAnnularRing_ThermalPadVias [IsVia and InAnyComponent] p1: minimumring=5.91
MinimumAnnularRing [All] p2: minimumring=6
MinimumSolderMaskSliver MinimumSolderMaskSliver_Logo [InComponentClass('Logo') vs InComponentClass('Logo')] p1: minsoldermaskwidth=0.7
MinimumSolderMaskSliver [All] p2: minsoldermaskwidth=0
PlaneConnect [All] p1: planeconnectstyle=Relief reliefexpansion=10 reliefentries=4 reliefconductorwidth=10 reliefairgap=10
PolygonConnect [All] p1: connectstyle=Direct reliefconductorwidth=10 reliefentries=4 polygonreliefangle="90 Angle" airgapwidth=10
RoutingVias ThermalPadVias [IsVia and InAnyComponent] p1: holewidth=7.87 width=19.68 viastyle="Through Hole" minholewidth=7.87 minwidth=19.68 maxholewidth=17 maxwidth=33
RoutingVias [All] p2: holewidth=10 width=22 viastyle="Through Hole" minholewidth=7.87 minwidth=22 maxholewidth=40 maxwidth=65
SilkToBoardRegionClearance [Not ((IsComment or IsDesignator) And (Hide <> 'False')) and not InRegion(1000,500,4000,800)] p1:
SilkToSilkClearance SilkToSilkClearance_Pb-FreeLogo [(HasFootprint('Pb-Free_Overlay_Medium') OR HasFootprint('Pb-Free_Overlay_Small')) vs (HasFootprint('Pb-Free_Overlay_Medium') OR HasFootprint('Pb-Free_Overlay_Small'))] p1: silktosilkclearance=0
SilkToSilkClearance [All] p2: silktosilkclearance=4
SilkToSolderMaskClearance SilkToComponentPadClearance [(IsPad or IsFill or IsRegion) and InAnycomponent] p1: minsilkscreentomaskgap=5 clearancetoexposedcopper=TRUE
SilkToSolderMaskClearance "Silk to Solder Mask Opening" [All] p2: minsilkscreentomaskgap=4 clearancetoexposedcopper=FALSE
SolderMaskExpansion [All] p1: expansion=1.97
Width [All] p1: maxlimit=100 minlimit=6 preferedwidth=10 checkconnectedcopper=TRUE
15 further rules are at their usual default settings.

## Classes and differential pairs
component class Header: J1
component class Designator: C30 C31 C32 C33 C34 C35 C36 C37 C38 C39 C40 C41 C42 C43 C44 C45 C46 C47 C48 C49 C50 C51 C52 C53 C54 C55 C56 C57 C58 C59 C60 D10 D11 D12 D13 D14 D15 J1 NT2 Q9 R39 R40 R41 R42 R43 R44 R45 R46 R47 R48 R49 R50 R51 R52 R53 R54 R55 R56 R57 R58 R59 R60 R61 R62 R63 R64 U7 U8 U9 U10 U11 U12 U13
component class Designator: "A to B" "B to A" C1 C2 C3 C4 C5 C6 C7 C8 C120 D1 D2 Q1 Q2 Q3 Q4 R1 R2 R3 R4 R5 R6 R7 R8 R9 R10 R11 R12 R13 R14 R15 U1 U2 U3
component class Designator: C9 C10 C11 C12 C13 C14 C15 D5 D6 Q5 Q6 R16 R17 R18 R19 R20 R21 R22 R23 R24 R25 R27 R28 U4
component class Designator: C110 C111 C112 C114 C115 C116 C117 C118 C119 C127 D25 D26 D27 D28 L10 L11 PGND Q18 Q19 Q20 Q21 Q22 Q23 Q24 Q25 R111 R112 R113 R114 R115 R116 R117 R118 R119 R120 R121 R122 R123 R124 R125 R126 R127 R128 R129 R130 R131 R132 R133 R134 V12_B
component class Designator: C92 C93 C94 C95 C96 C97 C98 C99 C100 C101 C102 C103 C104 C105 C106 C107 C108 C109 C121 C122 C123 C126 D21 D22 D23 D24 L8 L9 PGND Q10 Q11 Q12 Q13 Q14 Q15 Q16 Q17 R87 R88 R89 R90 R91 R92 R93 R94 R95 R96 R97 R98 R99 R100 R101 R102 R103 R104 R105 R106 R107 R108 R109 R110 V12_A
component class Designator: C61 C62 C63 C64 C65 C66 C67 C68 C69 C70 C71 C72 C73 C74 C75 C76 C77 C78 C79 C80 C82 C83 C84 C85 C86 C87 C88 C89 D16 D17 D18 D19 NT3 R65 R66 R67 R68 R69 R70 R71 R72 R73 R74 R75 R76 R77 R79 R80 R81 R82 R83 R84 R85 R86 U14 U15 U16 U17 U18

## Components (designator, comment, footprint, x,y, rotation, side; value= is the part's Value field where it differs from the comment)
"A to B" "150060YS75000" WL-SMCW_YELLOW 424.63,3608.42 r90 top value=Yellow
"B to A" "150060VS75000" WL-SMCW_GREEN 577.2,3607.2 r90 top value=Green
C1 "GRM188R72A104KA35D" 0603L 1283.39,3605 r270 top value=0.1uF
C2 "C0603C331J5GACTU" 0603 1213.39,3995 r180 top value=330pF
C3 "0603ZC100KAT2A" 0603 1149.68,3630 r0 top value=10pF
C4 "GRM188R71H183KA01D" 0603 1293.39,4025 r90 top value=0.018uF
C5 "GRM188R71H392KA01D" 0603 1223.39,3605 r270 top value=3900pF
C6 "08055C473KAT2A" 0805_HV 1049.68,3580 r270 top value=0.047uF
C7 "885012207092" 0805_HV 1079.68,4010 r180 top value=0.01uF
C8 "C1608C0G2A102J080AA" 0603L 4826.31,4196.3 r270 top value=1000pF
C9 "GRM188R72A104KA35D" 0603L 4289.06,3915.31 r180 top value=0.1uF
C10 "0603ZC100KAT2A" 0603 4405.72,3560 r0 top value=10pF
C11 "C0603C331J5GACTU" 0603 4414.06,4035.31 r180 top value=330pF
C12 "GRM188R71H392KA01D" 0603 4324.06,3530 r270 top value=3900pF
C13 "GRM188R71H183KA01D" 0603 4334.06,4060.31 r90 top value=0.018uF
C14 "885012207092" 0805_HV 4561.27,4082.8 r90 top value=0.01uF
C15 "08055C473KAT2A" 0805_HV 4614.38,3610 r270 top value=0.047uF
C16 "C2012X7S2A105K125AB" 0805_HV 5254.06,4140 r90 top value=1uF
C17 "C2012X7S2A105K125AB" 0805_HV 4958.75,4105 r180 top value=1uF
C18 "GRT31CR61H106KE01L" 1206_180 4583.75,2895 r180 top value=10uF
C19 "GRT31CR61H106KE01L" 1206_180 4583.75,2805 r180 top value=10uF
C20 "C2012X7R2A104K125AA" 0805_HV 5228.75,3674 r270 top value=0.1uF
C21 "C2012X7R2A104K125AA" 0805_HV 5146.62,3320 r180 top value=0.1uF
C22 "C2012X7R1C225K125AB" 0805_HV 5354.06,2630 r270 top value=2.2uF
C23 "C3216X5R1C476M160AB" 1206 5364.06,2630 r270 bottom value=47uF
C24 "GCJ216R71E182KA01D" 0603L 4808.75,3716.95 r0 top value=1800pF
C25 "GRM188R72A104KA35D" 0603L 4963.75,3879 r90 top value=0.1uF
C26 "GRM1885C1H361JA01D" 0603L 5023.75,3879 r90 top value=360pF
C27 "GRM188R71E105KA12D" 0603L 5043.75,3313.83 r270 top value=1uF
C28 "GRM188R71E105KA12D" 0603L 4988.75,3313.83 r270 top value=1uF
C29 "CGA3E2X7R1H683K080AA" 0603L 4848.75,3636.95 r90 top value=0.068uF
C30 "C1608C0G2A102J080AA" 0603L 2095,4075 r90 bottom value=1000pF
C31 "C1608C0G2A102J080AA" 0603L 2315,3965 r0 top value=1000pF
C32 "C1608C0G2A102J080AA" 0603L 2308.23,3580.94 r0 top value=1000pF
C33 "885012206081" 0603 2299.53,3462.2 r180 bottom value=470pF
C34 "GRM188R71E473KA01D" 0603 2298.86,3462.2 r180 top value=0.047uF
C35 "06031C103KAT2A" 0603L 2140.16,3990.94 r90 top value=0.01uF
C36 "C1608C0G2A102J080AA" 0603L 1610.16,3630.94 r180 top value=1000pF
C37 "C2012X7S2A105K125AB" 0805_HV 1739.53,3572.2 r0 bottom value=1uF
C38 "C2012X7S2A105K125AB" 0805_HV 1739.53,3662.2 r0 bottom value=1uF
C39 "GRM188R71C474KA88D" 0603L 2280.16,3742.2 r270 top value=0.47uF
C40 "C0603C101J5GACTU" 0603L 2360.16,3772.2 r0 top value=100pF
C41 "C0603C101J5GACTU" 0603L 2360.16,3712.2 r0 top value=100pF
C42 "GRM188R72A104KA35D" 0603L 4003.75,2995 r0 top value=0.1uF
C43 "C1608X7R1H224K080AB" 0603L 2120.16,3402.2 r270 top value=0.22uF
C44 "GRM188R72A104KA35D" 0603L 1480,250 r270 top value=0.1uF
C45 "C2012X7R1C225K125AB" 0805_HV 1950,3254.61 r270 top value=2.2uF
C46 "GRM188R71E105KA12D" 0603L 2310.16,3630.94 r0 bottom value=1uF
C47 "GRM188R72A104KA35D" 0603L 2777.05,635 r180 bottom value=0.1uF
C48 "C1608X7R1H224K080AB" 0603L 1800.16,3402.2 r90 top value=0.22uF
C49 "06031C103KAT2A" 0603L 1929.53,3992.2 r90 top value=0.01uF
C50 "06031C103KAT2A" 0603L 1615.73,3492.2 r180 bottom value=0.01uF
C51 "GRM188R71C474KA88D" 0603L 1628.5,3740.55 r90 top value=0.47uF
C52 "C0603C101J5GACTU" 0603L 1548.5,3710.55 r180 top value=100pF
C53 "C0603C101J5GACTU" 0603L 1548.5,3770.55 r180 top value=100pF
C54 "GRM188R71E473KA01D" 0603 1610.16,3550.94 r180 top value=0.047uF
C55 "GRM188R72A104KA35D" 0603L 1555,2815 r0 top value=0.1uF
C56 "C0603C101J5GACTU" 0603L 1460.16,3610.95 r180 top value=100pF
C57 "C0603C101J5GACTU" 0603L 2300.16,3400.94 r0 bottom value=100pF
C58 "885012206081" 0603 1615.73,3492.87 r180 top value=470pF
C59 "06031C103KAT2A" 0603L 2080.16,3990.94 r90 top value=0.01uF
C60 "C0603C101J5GACTU" 0603L 4151.35,2899.92 r0 top value=100pF
C61 "C1608C0G2A102J080AA" 0603L 3903.75,3601.3 r0 top value=1000pF
C62 "C1608C0G2A102J080AA" 0603L 3583.75,4018.7 r180 bottom value=1000pF
C63 "C1608C0G2A102J080AA" 0603L 3875,3995 r0 top value=1000pF
C64 "885012206081" 0603 3898.2,3480 r180 bottom value=470pF
C65 "GRM188R71E473KA01D" 0603 3898.2,3480 r180 top value=0.047uF
C66 "C1608C0G2A102J080AA" 0603L 3193.75,3630 r180 top value=1000pF
C67 "06031C103KAT2A" 0603L 3763.75,4000 r90 bottom value=0.01uF
C68 "C2012X7S2A105K125AB" 0805_HV 3323.75,3580 r180 bottom value=1uF
C69 "C2012X7S2A105K125AB" 0805_HV 3323.75,3670 r0 bottom value=1uF
C70 "GRM188R71C474KA88D" 0603L 3876.55,3762.8 r270 top value=0.47uF
C71 "C0603C101J5GACTU" 0603L 3956.55,3792.8 r0 top value=100pF
C72 "C0603C101J5GACTU" 0603L 3956.55,3732.8 r0 top value=100pF
C73 "C1608X7R1H224K080AB" 0603L 3713.75,3410 r270 top value=0.22uF
C74 "GRM188R72A104KA35D" 0603L 2775,2530 r180 bottom value=0.1uF
C75 "C2012X7R1C225K125AB" 0805_HV 3543.75,3280 r270 top value=2.2uF
C76 "GRM188R72A104KA35D" 0603L 3693.75,190 r90 top value=0.1uF
C77 "GRM188R71E105KA12D" 0603L 3903.75,3670 r0 top value=1uF
C78 "C1608X7R1H224K080AB" 0603L 3393.75,3410 r90 top value=0.22uF
C79 "06031C103KAT2A" 0603L 3523.75,4000 r90 top value=0.01uF
C80 "06031C103KAT2A" 0603L 3188,3500 r180 bottom value=0.01uF
C82 "GRM188R71C474KA88D" 0603L 3230.93,3770.73 r90 top value=0.47uF
C83 "C0603C101J5GACTU" 0603L 3156.54,3732.8 r180 top value=100pF
C84 "C0603C101J5GACTU" 0603L 3156.54,3792.8 r180 top value=100pF
C85 "GRM188R71E473KA01D" 0603 3189.3,3554.41 r180 top value=0.047uF
C86 "C0603C101J5GACTU" 0603L 3063.75,3610 r180 top value=100pF
C87 "C0603C101J5GACTU" 0603L 3895.05,3420 r0 top value=100pF
C88 "885012206081" 0603 3188,3500 r180 top value=470pF
C89 "06031C103KAT2A" 0603L 3704.24,4000 r90 top value=0.01uF
C92 "08051A101KAT2A" 0805_HV 2013.15,2942.48 r0 top value=100pF
C93 "08051A101KAT2A" 0805_HV 2030,195 r0 top value=100pF
C94 "PCR1H181MCL1GS" CR_1000x1270 555,295 r180 top value=180uF
C95 "PCR1H181MCL1GS" CR_1000x1270 555,740 r180 top value=180uF
C96 "PCR1H181MCL1GS" CR_1000x1270 554.99,295 r180 bottom value=180uF
C97 "PCR1H181MCL1GS" CR_1000x1270 554.99,740 r180 bottom value=180uF
C98 "C5750X7R2A475M230KA" 2220_280 1250,1930 r0 top value=4.7uF
C99 "C5750X7R2A475M230KA" 2220_280 1250,1452.38 r0 top value=4.7uF
C100 "C5750X7R2A475M230KA" 2220_280 1250,1694.75 r0 top value=4.7uF
C101 "C5750X7R2A475M230KA" 2220_280 1250,1210 r0 top value=4.7uF
C102 "PCR1H181MCL1GS" CR_1000x1270 3265,1340 r0 top value=180uF
C103 "PCR1H181MCL1GS" CR_1000x1270 2265,1745 r180 top value=180uF
C104 "PCR1H181MCL1GS" CR_1000x1270 3260,1785 r0 top value=180uF
C105 "PCR1H181MCL1GS" CR_1000x1270 2265,1301.14 r180 top value=180uF
C106 "C5750X7R2A475M230KA" 2220_280 3265,1390 r0 bottom value=4.7uF
C107 "C5750X7R2A475M230KA" 2220_280 2309.94,1197.79 r180 bottom value=4.7uF
C108 "C5750X7R2A475M230KA" 2220_280 3265,1865 r0 bottom value=4.7uF
C109 "C5750X7R2A475M230KA" 2220_280 2309.94,1672.79 r180 bottom value=4.7uF
C110 "08051A101KAT2A" 0805_HV 3863.47,2939.41 r0 top value=100pF
C111 "08051A101KAT2A" 0805_HV 4043.75,146.69 r0 top value=100pF
C112 "PCR1H181MCL1GS" CR_1000x1270 5163.75,810 r0 top value=180uF
C114 "PCR1H181MCL1GS" CR_1000x1270 5163.75,809.99 r0 bottom value=180uF
C115 "PCR1H181MCL1GS" CR_1000x1270 5158.75,355 r0 bottom value=180uF
C116 "C5750X7R2A475M230KA" 2220_280 4383.75,1300 r180 top value=4.7uF
C117 "C5750X7R2A475M230KA" 2220_280 4378.75,1784.75 r180 top value=4.7uF
C118 "C5750X7R2A475M230KA" 2220_280 4378.75,1542.38 r180 top value=4.7uF
C119 "C5750X7R2A475M230KA" 2220_280 4381.31,2027.13 r180 top value=4.7uF
C120 "GRM188R72A104KA35D" 0603L 705,3905.31 r90 top value=0.1uF
C121 "C5750X7R2A475M230KA" 2220_280 2309.09,1915.94 r180 bottom value=4.7uF
C122 "C5750X7R2A475M230KA" 2220_280 3265,1625 r0 bottom value=4.7uF
C123 "C5750X7R2A475M230KA" 2220_280 3260,1150 r0 bottom value=4.7uF
C126 "C5750X7R2A475M230KA" 2220_280 2309.94,1437.79 r180 bottom value=4.7uF
C127 "PCR1H181MCL1GS" CR_1000x1270 5158.75,355 r0 top value=180uF
D1 "CMDD4448" sod-323 1308.39,3905 r90 top value=75V
D2 "CMDD4448" sod-323 1308.39,3735 r270 top value=75V
D5 "CMDD4448" sod-323 4299.06,3650.31 r270 top value=75V
D6 "CMDD4448" sod-323 4299.06,3810.31 r90 top value=75V
D7 "1N4148W-TP" SOD-123 5243.75,3500 r90 top value=100V
D8 "SS16T3G" SMA 5348.75,2885 r90 top value=60V
D9 "SS16T3G" SMA 4748.75,3100 r90 top value=60V
D10 "CMDD4448" sod-323 2001.1,4146.22 r180 bottom value=75V
D11 "CMDD4448" sod-323 2470.16,3981.26 r0 top value=75V
D12 "PMEG6010CEH,115" SOD-123F 2050.16,3250.94 r90 top value=60V
D13 "PMEG6010CEH,115" SOD-123F 1855,3249.61 r90 top value=60V
D14 "1N4148X-TP" SOD-523 4155,2830 r0 top value=75V
D15 "BZT52C5V1S-7-F" SOD-323 975,3155 r90 top value=5.1V
D16 "CMDD4448" sod-323 3434.24,4021.95 r180 bottom value=75V
D17 "CMDD4448" sod-323 3993.75,3980 r270 top value=75V
D18 "PMEG6010CEH,115" SOD-123F 3638.75,3275 r90 top value=60V
D19 "PMEG6010CEH,115" SOD-123F 3448.75,3275 r90 top value=60V
D21 "FSV360FP" SOD-123HE 1768.68,2215 r270 top value=60V
D22 "FSV360FP" SOD-123HE 2255,2820 r180 top value=60V
D23 "FSV360FP" SOD-123HE 1860,890 r90 top value=60V
D24 "FSV360FP" SOD-123HE 2270,945 r180 top value=60V
D25 "FSV360FP" SOD-123HE 3720,2275 r270 top value=60V
D26 "FSV360FP" SOD-123HE 3305,2105 r0 top value=60V
D27 "FSV360FP" SOD-123HE 3840,825 r90 top value=60V
D28 "FSV360FP" SOD-123HE 3375,240 r0 top value=60V
J1 "804-10-021-10-002000" Mill-Max_804-10-021-10-002000 555,3110 r90 top
L1 "MSS1048-154KLB" MSS1048 5053.75,2990 r0 top value=150uH
L8 "ERU33" ERU33 1537.6,2724.92 r0 bottom
L9 "ERU33" ERU33 1555,385 r180 bottom
L10 "ERU33" ERU33 4110,2680 r0 bottom
L11 "ERU33" ERU33 4102.33,429.12 r180 bottom
NT1 "Net-Tie" Net-Tie_10mil 5018.75,3664 r270 top net-tie
NT2 "Net-Tie" Net-Tie_10mil 1950.16,3520.94 r270 top net-tie
NT3 "Net-Tie" Net-Tie_10mil 3543.75,3540 r270 top net-tie
PGND "CXS70-14-C" Panduit_CXS70-14-C 515,1990 r0 top
PGND "CXS70-14-C" Panduit_CXS70-14-C 5115.04,2075 r180 top
Q1 "2N7002E-T1-E3" SOT-23 919.68,4030 r90 top value=60V
Q2 "2N7002E-T1-E3" SOT-23 869.68,3580 r90 top value=60V
Q3 "2N7002E-T1-E3" SOT-23 424.63,3438.42 r90 top value=60V
Q4 "2N7002E-T1-E3" SOT-23 577.2,3437.2 r90 top value=60V
Q5 "2N7002E-T1-E3" SOT-23 4538.75,3345 r90 top value=60V
Q6 "2N7002E-T1-E3" SOT-23 4684.06,4140.31 r270 top value=60V
Q7 "BSR606NH6327XTSA1" SOT-23 4738.75,2880 r180 top value=60V
Q8 "BSR606NH6327XTSA1" SOT-23 5343.75,3085 r270 top value=60V
Q9 "BSS123W-7-F" SOT-323 1840.16,3960.94 r90 bottom value=100V
Q10 "NVMFS5C628NLT1G" PG-TDSON-8 2308.15,2637.48 r0 top
Q11 "NVMFS5C628NLT1G" PG-TDSON-8 1945.47,2168.39 r90 top
Q12 "NVMFS5C628NLT1G" PG-TDSON-8 1585,2175 r90 top
Q13 "NVMFS5C628NLT1G" PG-TDSON-8 2310,2285 r0 top
Q14 "NVMFS5C628NLT1G" PG-TDSON-8 2325,405 r0 top
Q15 "NVMFS5C628NLT1G" PG-TDSON-8 2043.15,932.48 r270 top
Q16 "NVMFS5C628NLT1G" PG-TDSON-8 1679.06,935 r270 top
Q17 "NVMFS5C628NLT1G" PG-TDSON-8 2325.51,761.89 r0 top
Q18 "NVMFS5C628NLT1G" PG-TDSON-8 3261.9,2640.51 r180 top
Q19 "NVMFS5C628NLT1G" PG-TDSON-8 3905,2215 r90 top
Q20 "NVMFS5C628NLT1G" PG-TDSON-8 3538.55,2214.72 r90 top
Q21 "NVMFS5C628NLT1G" PG-TDSON-8 3241.07,2287.91 r180 top
Q22 "NVMFS5C628NLT1G" PG-TDSON-8 3310.48,774.65 r180 top
Q23 "NVMFS5C628NLT1G" PG-TDSON-8 4020,870 r270 top
Q24 "NVMFS5C628NLT1G" PG-TDSON-8 3663.98,872.24 r270 top
Q25 "NVMFS5C628NLT1G" PG-TDSON-8 3312.45,422.48 r180 top
R1 "RC0603FR-0717K8L" 0603L 1268.39,4110 r180 top value=17.8k
R2 "CRCW060337K4FKEA" 0603L 1203.39,3520 r0 top value=37.4k
R3 "RC0603FR-072K2L" 0603 1189.68,4140 r270 top value=2.20k
R4 "RC0603FR-077K5L" 0603 1118.39,3495 r90 top value=7.50k
R5 "RC0603FR-079K09L" 0603 1213.39,4050 r180 top value=9.09k
R6 "RC0603FR-0759KL" 0603 1148.39,3575 r0 top value=59.0k
R7 "RC0603FR-07499RL" 0603 1390,3874.43 r90 top value=499
R8 "RC0603FR-07200KL" 0603 1129.68,4110 r90 top value=200k
R9 "RC0603FR-07200KL" 0603 979.68,3600 r90 top value=200k
R10 "CRCW060310K0FKEA" 0603L 1390,3979.43 r90 top value=10.0k
R11 "CRCW060320R0FKEA" 0603L 979.68,3690 r0 top value=20.0
R12 "CRCW060320R0FKEA" 0603L 1049.68,4080 r0 top value=20.0
R13 "CRCW06034K99FKEA" 0603L 424.63,3718.42 r270 top value=4.99k
R14 "CRCW06034K99FKEA" 0603L 4826.31,4311.3 r270 top value=4.99k
R15 "CRCW06034K99FKEA" 0603L 577.2,3717.2 r270 top value=4.99k
R16 "CRCW060337K4FKEA" 0603L 4344.06,3440.31 r0 top value=37.4k
R17 "RC0603FR-0717K8L" 0603L 4439.06,4180.31 r90 top value=17.8k
R18 "RC0603FR-077K5L" 0603 4429.06,3410.31 r90 top value=7.50k
R19 "RC0603FR-072K2L" 0603 4359.06,4150.31 r0 top value=2.20k
R20 "RC0603FR-0759KL" 0603 4401.26,3502.8 r0 top value=59.0k
R21 "RC0603FR-079K09L" 0603 4409.06,4090.31 r180 top value=9.09k
R22 "RC0603FR-07499RL" 0603 4205.36,3789.45 r90 top value=499
R23 "RC0603FR-07200KL" 0603 4563.75,3505 r0 top value=200k
R24 "RC0603FR-07200KL" 0603 4664.06,3985.31 r180 top value=200k
R25 "CRCW060310K0FKEA" 0603L 4205.36,3894.45 r90 top value=10.0k
R27 "CRCW060320R0FKEA" 0603L 4664.38,4040 r180 top value=20.0
R28 "CRCW060320R0FKEA" 0603L 4484.06,3480 r90 top value=20.0
R30 "CRCW060375K0FKEA" 0603L 5168.75,3804 r0 top value=75.0k
R31 "CRCW060329K4FKEA" 0603L 5138.75,3879 r270 top value=29.4k
R32 "RC0603FR-071K07L" 0603 5023.75,3879 r270 bottom value=1.07k
R33 "CRCW060318K2FKEA" 0603L 5083.75,3879 r270 top value=18.2k
R34 "RL1632R-R220-F" 1206 4783.75,3275 r180 top value=0.22
R35 "RC0603FR-0718K2L" 0603 4788.75,3636.95 r90 top value=18.2k
R36 "CRCW0603732RFKEA" 0603L 4908.75,3880 r270 top value=732
R37 "CRCW06035K23FKEA" 0603L 4853.75,3880 r90 top value=5.23k
R38 "CRCW060310R0FKEA" 0603L 4938.75,3955 r0 top value=10.0
R39 "CRCW060395K3FKEA" 0603L 2308.23,3522.2 r180 top value=95.3k
R40 "CRCW06034K99FKEA" 0603L 2010,4070 r0 bottom value=4.99k
R41 "RC0603FR-072K4L" 0603 2107.72,3963.39 r180 bottom value=2.40k
R42 "CRCW06034K99FKEA" 0603L 2459.29,4063.01 r180 top value=4.99k
R43 "RC0603FR-072K4L" 0603 2200.16,3990.94 r270 top value=2.40k
R44 "RC0603FR-071K5L" 0603 2398.86,3462.2 r0 top value=1.50k
R45 "CRCW060395K3FKEA" 0603L 1690.16,3652.2 r270 top value=95.3k
R46 "RC0603FR-072K94L" 0603 2207.72,3963.39 r180 bottom value=2.94k
R47 "RC0603FR-072K94L" 0603 2198.84,4133.46 r270 top value=2.94k
R48 "RC0603FR-0720KL" 0603 2467.36,3672.2 r90 top value=20.0k
R49 "RC0603FR-0720KL" 0603 2467.36,3672.2 r90 bottom value=20.0k
R50 "CRCW0402100KFKED" 0402 4018.75,2945 r180 top value=100k
R51 "CRCW060349K9FKEA" 0603L 1853.53,4068.2 r0 bottom value=49.9k
R52 "RC0603FR-079K76L" 0603 1809.53,3992.2 r90 top value=9.76k
R53 "RC0805FR-072RL" 0805_HV 2145,3254.61 r270 top value=2.00
R54 "CRCW060310K0FKEA" 0603L 1990.85,3993.88 r270 top value=10.0k
R55 "RC0603FR-0740K2L" 0603 1870,3995 r270 top value=40.2k
R56 "CRCW080524R9FKEA" 0805L 2312.96,3645 r0 top value=24.9
R57 "RC0603FR-0773K2L" 0603 2308.23,3570.94 r180 bottom value=73.2k
R58 "RC0805FR-072RL" 0805_HV 1760,3254.61 r270 top value=2.00
R59 "RC0603FR-0710K5L" 0603L 220,2900 r180 top value=10.5k
R60 "RC0603FR-0791KL" 0603 1460.16,3610.95 r0 bottom value=91.0k
R61 "RC0603FR-0730K9L" 0603 2300.16,3400.94 r180 top value=30.9k
R62 "RC0603FR-071K5L" 0603 1515.73,3552.2 r0 top value=1.50k
R63 "RC0603FR-0720KL" 0603 990,3010 r180 top value=20.0k
R64 "RC0603FR-0710K5L" 0603L 960,2920 r90 top value=10.5k
R65 "CRCW060395K3FKEA" 0603L 3903.75,3540 r180 top value=95.3k
R66 "CRCW06034K99FKEA" 0603L 3474.24,4121.95 r270 bottom value=4.99k
R67 "RC0603FR-072K4L" 0603 3704.25,4000 r270 bottom value=2.40k
R68 "CRCW06034K99FKEA" 0603L 3983.75,4114.43 r270 top value=4.99k
R69 "RC0603FR-072K4L" 0603 3763.75,4000 r270 top value=2.40k
R70 "RC0603FR-071K5L" 0603 4008.2,3480 r0 top value=1.50k
R71 "CRCW060395K3FKEA" 0603L 3273.75,3660 r270 top value=95.3k
R72 "RC0603FR-072K94L" 0603 3704.25,4100 r270 bottom value=2.94k
R73 "RC0603FR-072K94L" 0603 3763.75,4100 r270 top value=2.94k
R74 "RC0603FR-0720KL" 0603 4065,3690 r90 top value=20.0k
R75 "RC0603FR-0720KL" 0603 4060,3695 r90 bottom value=20.0k
R76 "RC0603FR-079K76L" 0603 3403.75,4000 r90 top value=9.76k
R77 "RC0805FR-072RL" 0805_HV 3733.75,3280 r270 top value=2.00
R79 "CRCW060310K0FKEA" 0603L 3583.75,4000 r270 top value=10.0k
R80 "RC0603FR-0740K2L" 0603 3463.75,4000 r270 top value=40.2k
R81 "CRCW080524R9FKEA" 0805L 3903.75,3640 r0 bottom value=24.9
R82 "RC0603FR-0773K2L" 0603 3903.75,3570 r180 bottom value=73.2k
R83 "RC0805FR-072RL" 0805_HV 3353.75,3280 r270 top value=2.00
R84 "RC0603FR-0791KL" 0603 3063.75,3610 r0 bottom value=91.0k
R85 "RC0603FR-0730K9L" 0603 3895.05,3420 r180 bottom value=30.9k
R86 "RC0603FR-071K5L" 0603 3089.3,3555.71 r0 top value=1.50k
R87 "CSS2725FT1L00" CSS2725_001 1053.15,2217.48 r90 top value=0.001
R88 "CRCW060349K9FKEA" 0603 2125,2580 r90 top value=49.9k
R89 "CRCW121810R0FKEK" 1218 1818.15,2887.48 r270 top value=10.0
R90 "CRCW060349K9FKEA" 0603 1995,1980 r0 top value=49.9k
R91 "CRCW060349K9FKEA" 0603 1660,1985 r0 top value=49.9k
R92 "RC0603FR-071RL" 0603 2305.81,3719.67 r0 bottom value=1.00
R93 "RC0603FR-071RL" 0603 2305.81,3777.23 r0 bottom value=1.00
R94 "CRCW08051R00FKEA" 0805_HV 2235,2460 r180 top value=1.00
R95 "CRCW08051R00FKEA" 0805_HV 2115,2040 r90 top value=1.00
R96 "CRCW08051R00FKEA" 0805_HV 1775,2020 r90 top value=1.00
R97 "CRCW060349K9FKEA" 0603 2125,2230 r90 top value=49.9k
R98 "CRCW08051R00FKEA" 0805_HV 2240,2110 r180 top value=1.00
R99 "CSS2725FT1L00" CSS2725_001 1148.15,857.48 r270 top value=0.001
R100 "CRCW060349K9FKEA" 0603 2135,350 r90 top value=49.9k
R101 "CRCW121810R0FKEK" 1218 1810,250 r90 top value=10.0
R102 "RC0603FR-071RL" 0603 1603.5,3712.99 r180 bottom value=1.00
R103 "RC0603FR-071RL" 0603 1603.5,3768.11 r180 bottom value=1.00
R104 "CRCW060349K9FKEA" 0603 1985,1120 r0 top value=49.9k
R105 "CRCW060349K9FKEA" 0603 1650,1122.83 r0 top value=49.9k
R106 "CRCW08051R00FKEA" 0805_HV 2255,230 r180 top value=1.00
R107 "CRCW08051R00FKEA" 0805_HV 1875,1085 r270 top value=1.00
R108 "CRCW08051R00FKEA" 0805_HV 1505,1085 r270 top value=1.00
R109 "CRCW060349K9FKEA" 0603 2135,710 r90 top value=49.9k
R110 "CRCW08051R00FKEA" 0805_HV 2255,585 r180 top value=1.00
R111 "CSS2725FT1L00" CSS2725_001 4599.97,2402.01 r270 top value=0.001
R112 "CRCW060349K9FKEA" 0603 3450,2695 r270 top value=49.9k
R113 "CRCW121810R0FKEK" 1218 3668.47,2884.41 r270 top value=10.0
R114 "CRCW060349K9FKEA" 0603 3955,2025 r0 top value=49.9k
R115 "CRCW060349K9FKEA" 0603 3590,2030 r0 top value=49.9k
R116 "RC0603FR-071RL" 0603 3909.3,3792.8 r0 bottom value=1.00
R117 "RC0603FR-071RL" 0603 3909.3,3735 r0 bottom value=1.00
R118 "CRCW08051R00FKEA" 0805_HV 3335,2815 r0 top value=1.00
R119 "CRCW08051R00FKEA" 0805_HV 4075,2065 r90 top value=1.00
R120 "CRCW08051R00FKEA" 0805_HV 3705,2060 r90 top value=1.00
R121 "CRCW060349K9FKEA" 0603 3390,2445 r0 top value=49.9k
R122 "CRCW08051R00FKEA" 0805_HV 3245,2465 r0 top value=1.00
R123 "CSS2725FT1L00" CSS2725_001 4599.59,936.52 r90 top value=0.001
R124 "CRCW060349K9FKEA" 0603 3495,830 r270 top value=49.9k
R125 "CRCW121810R0FKEK" 1218 3853.75,195 r90 top value=10.0
R126 "RC0603FR-071RL" 0603 3203.79,3792.8 r180 bottom value=1.00
R127 "RC0603FR-071RL" 0603 3203.79,3740 r180 bottom value=1.00
R128 "CRCW060349K9FKEA" 0603 3965,1055 r0 top value=49.9k
R129 "CRCW060349K9FKEA" 0603 3605,1055 r0 top value=49.9k
R130 "CRCW08051R00FKEA" 0805_HV 3375,950 r0 top value=1.00
R131 "CRCW08051R00FKEA" 0805_HV 3850,1025 r270 top value=1.00
R132 "CRCW08051R00FKEA" 0805_HV 3495,1020 r270 top value=1.00
R133 "CRCW060349K9FKEA" 0603 3495,480 r270 top value=49.9k
R134 "CRCW08051R00FKEA" 0805_HV 3385,595 r0 top value=1.00
U1 "LM6142AIM" D0008A_N 1149.68,3810 r270 top
U2 "SN74LV00ADR" D0014A_N 485,4005.31 r270 top
U3 "LM4040AIM3X-2.0" MF03A_N 4931.31,4245 r0 top
U4 "LM6142AIM" D0008A_N 4454.06,3800 r90 top
U5 "TPS70950DBVR" DBV0005A_N 5124.06,4140 r180 top
U6 "LM5118MH/NOPB" MXA20A_N 5033.75,3594 r270 top
U7 "LMV431BIMF/NOPB" DBZ0003A_N 2198.84,4072.44 r0 bottom
U8 "LMV431BIMF/NOPB" DBZ0003A_N 2315,4070 r90 top
U9 "LM5170" PHP0048D_L 1960.16,3642.2 r0 top
U10 "LM26LVCISD-145/NOPB" SDB06A 4021.35,2854.92 r180 top
U11 "LM26LVCISD-145/NOPB" SDB06A 1580,260 r180 top
U12 "LM26LVCISD-145/NOPB" SDB06A 2755.97,537.44 r0 bottom
U13 "LM26LVCISD-145/NOPB" SDB06A 1575,2720 r180 top
U14 "LMV431BIMF/NOPB" DBZ0003A_N 3585,4120 r90 bottom
U15 "LMV431BIMF/NOPB" DBZ0003A_N 3875,4095 r90 top
U16 "LM5170" PHP0048D_L 3553.75,3650 r0 top
U17 "LM26LVCISD-145/NOPB" SDB06A 2755,2435.28 r0 bottom
U18 "LM26LVCISD-145/NOPB" SDB06A 3589.77,187.56 r0 top
V12_A "CXS70-14-C" Panduit_CXS70-14-C 534.96,1245 r0 top
V12_B "CXS70-14-C" Panduit_CXS70-14-C 5120.04,1310 r180 top

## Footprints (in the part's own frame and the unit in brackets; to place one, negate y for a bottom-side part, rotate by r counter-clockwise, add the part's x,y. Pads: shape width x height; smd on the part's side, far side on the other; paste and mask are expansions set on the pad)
0402 [mm] "0402 from SM-752 data"
  rect 0.8x0.6 smd: 1(-0.6,0) 2(0.6,0)
  silkscreen extent -1.22,-0.52 1.22,0.52, body extent -0.55,-0.3 0.55,0.3, height 0.6
0603 [mm] "0603 from SM-752 data"
  rect 1x0.95 smd: 1(-0.8,0) 2(0.8,0)
  silkscreen extent -1.52,-0.69 1.52,0.69, body extent -0.87,-0.47 0.87,0.47, height 1
0603L [mm] "0603 from SM-752 data"
  rect 0.8x0.85 smd: 1(-0.7,0) 2(0.7,0)
  silkscreen extent -0.07,-0.33 0.07,0.33, body extent -0.87,-0.47 0.87,0.47, height 1
0805_HV [mil] "0805 with 30mil clearance between pads"
  rect 50x63 smd: 1(-40,0) 2(40,0)
  silkscreen extent -74,-40 74,40, body extent -43,-29 43,29, height 57
0805L [mm] "0805 from SM-752 data"
  rect 1.1x1.4 smd: 1(-0.75,0) 2(0.75,0)
  body extent -1.1,-0.72 1.1,0.72, height 1.45
1206 [mm] "1206 from SM-752 data"
  rect 1.3x1.85 smd: 1(-1.45,0) 2(1.45,0)
  silkscreen extent -2.4,-1.21 2.4,1.21, body extent -1.7,-0.9 1.7,0.9, height 1.35
1206_180 [mm] "1206_180"
  rect 1.1x1.6 smd: 1(-1.7,0) 2(1.7,0)
  silkscreen extent -0.9,-1 0.9,1, body extent -1.75,-0.95 1.75,0.95, height 1.8
1218 [mil] "Vishay recommended land pattern for 1218, document number 20008 revision 13-Oct-08"
  rect 40x187 smd: 1(-59,0) 2(59,0)
  silkscreen extent -94,-110 94,110, body extent -65,-93 65,93, height 24
2220_280 [mm] "Chip Capacitor, Body 5.7x5.0mm, IPC Medium Density"
  rect 1.6x5.3 smd: 1(-2.6,0) 2(2.6,0)
  silkscreen extent -3.69,-2.94 3.69,2.94, body extent -2.95,-2.62 2.95,2.62, height 2.8
CR_1000x1270 [mm] "SMD, 2-Leads, Dia 10.5mm, Pin Spacing 8mm"
  rect 4x2 smd: 1(-4,0) 2(4,0)
  silkscreen extent -7.4,-5.25 5.25,5.25, body extent -5.25,-5.25 5.25,5.25, height 12.71
CSS2725_001 [mm] "STACKPOLE ELECTRONICS"
  rect 3.18x6.86 smd: 1(-2.25,0) 2(2.25,0)
  silkscreen extent -4.13,-3.7 4.13,3.7, body extent -3.53,-3.35 3.53,3.35, height 1.34
D0008A_N [mm] "SOIC, 8-Leads, Body 4.9x3.9mm, Pitch 1.27mm, IPC Medium Density"
  oval 1.45x0.6 smd: 1(-2.725,1.905) 2(-2.725,0.635) 3(-2.725,-0.635) 4(-2.725,-1.905) 5(2.725,-1.905) 6(2.725,-0.635) 7(2.725,0.635) 8(2.725,1.905)
  silkscreen extent -3.3,-2.5 0.9,2.5, body extent -3,-2.45 3,2.45, height 1.63
D0014A_N [mm] "SOIC, 14-Leads, Body 8.7x3.9mm, Pitch 1.27mm, IPC Medium Density"
  oval 1.45x0.6 smd: 1(-2.725,3.81) 2(-2.725,2.54) 3(-2.725,1.27) 4(-2.725,0) 5(-2.725,-1.27) 6(-2.725,-2.54) 7(-2.725,-3.81) 8(2.725,-3.81) 9(2.725,-2.54) 10(2.725,-1.27) 11(2.725,0) 12(2.725,1.27) 13(2.725,2.54) 14(2.725,3.81)
  silkscreen extent -3.3,-4.4 0.9,4.4, body extent -3.02,-4.32 3.02,4.32, height 1.6
DBV0005A_N [mm] "SOT23, 5-Leads, Body 2.9x1.6mm, Pitch 0.95mm, Lead Span 2.8mm, IPC Medium Density"
  rrect17% 1x0.6 smd: 1(-1.375,0.95) 2(-1.375,0) 3(-1.375,-0.95) 4(1.375,-0.95) 5(1.375,0.95)
  silkscreen extent -1.63,-1.55 0.38,1.55, body extent -1.42,-1.46 1.42,1.46, height 1.09
DBZ0003A_N [mm] "SOT23, 3-Leads, Body 2.9x1.3mm, Pitch 0.95mm, Lead Span 2.4mm, IPC Medium Density"
  rrect17% 1x0.6 smd: 1(-1.2,0.95) 2(-1.2,-0.95) 3(1.2,0)
  silkscreen extent 0.2,-1.5 0.7,1.5, body extent -1.26,-1.46 1.26,1.46, height 0.98
ERU33 [mm]
  rect 4.45x8.9 smd: 1(-11.3,1.95) 2(11.3,1.95)
  silkscreen extent -17,-2.5 17,16.9
MF03A_N [mm] "SOT23, 3-Leads, Body 2.9x1.3mm, Pitch 0.95mm, Lead Span 2.4mm, IPC Medium Density"
  rect 1.3x0.6 smd: 1(-1.05,0.95) 2(-1.05,-0.95) 3(1.05,0)
  silkscreen extent -1.17,-1.5 0.7,1.92, body extent -0.7,-1.5 0.7,1.5, height 1.12
Mill-Max_804-10-021-10-002000 [mm] "Header, 2.54 mm, 7x3, TH"
  rect 1.4x1.4 hole 0.9: 1(-2.54,7.62)
  round 1.4 hole 0.9: 2(0,7.62) 3(2.54,7.62) 4(-2.54,5.08) 5(0,5.08) 6(2.54,5.08) 7(-2.54,2.54) 8(0,2.54) 9(2.54,2.54) 10(-2.54,0) 11(0,0) 12(2.54,0) 13(-2.54,-2.54) 14(0,-2.54) 15(2.54,-2.54) 16(-2.54,-5.08) 17(0,-5.08) 18(2.54,-5.08) 19(-2.54,-7.62) 20(0,-7.62) 21(2.54,-7.62)
  silkscreen extent -4.25,-8.89 3.79,8.89, body extent -3.81,-8.89 3.81,8.89, height 6.79
MSS1048 [mm] "Coilcraft recommended land pattern Document 462-2 Revised 06/09/09"
  rect 1.78x3.56 smd: 1(-4.7,0) 2(4.7,0)
  silkscreen extent -5.71,-5.59 5.71,5.59, body extent -5.15,-5.1 5.15,5.1, height 5.12
MXA20A_N [mm] "TSOP, 20-Leads, Body 6.5x4.4mm, Pitch 0.65mm, Exposed Pad, IPC Medium Density"
  oval 1.7x0.35 smd: 1(-2.85,2.925) 2(-2.85,2.275) 3(-2.85,1.625) 4(-2.85,0.975) 5(-2.85,0.325) 6(-2.85,-0.325) 7(-2.85,-0.975) 8(-2.85,-1.625) 9(-2.85,-2.275) 10(-2.85,-2.925) 11(2.85,-2.925) 12(2.85,-2.275) 13(2.85,-1.625) 14(2.85,-0.975) 15(2.85,-0.325) 16(2.85,0.325) 17(2.85,0.975) 18(2.85,1.625) 19(2.85,2.275) 20(2.85,2.925)
  rect 3x4.2 smd: 21(0,0)
  silkscreen extent -2.97,-3.3 1.6,3.78, body extent -2.25,-3.3 2.25,3.3, height 1.1
Net-Tie_10mil [mil] "10mil net tie, no solder mask opening, no solder paste"
  rect 10x10 smd paste-5 mask-5: 1(-10,0) 2(10,0)
  Top Layer region: -6,5 6,5 6,-5 -6,-5
Panduit_CXS70-14-C [mil] "Panduit"
  rect 770x500 hole 270 copper offset -74.8,0 paste-250: 1(0,0)
  body extent -960,-250 310,250, height 684
PG-TDSON-8 [mm] "Infineon recommended land pattern"
  rect 1.2x0.65 smd: 1(-2.825,1.905) 2(-2.825,0.635) 3(-2.825,-0.635) 4(-2.825,-1.905)
  rect 0.5x0.7 smd: 5(3.175,-2) 6(3.175,-0.675) 7(3.175,0.675) 8(3.175,2)
  rect 4.5x4.7 smd paste-2.25: 9(0.675,0)
  silkscreen extent -3.74,-3 3.74,3, body extent -3.17,-2.89 3.17,2.9, height 1.1
PHP0048D_L [mm] "Thin QFP, 48-Leads, Body 7x7mm, Pitch 0.5mm, Thermal Pad 4.5x4.5mm, IPC High Density"
  rrect100% 1.25x0.3 smd: 1(-4.125,2.75) 2(-4.125,2.25) 3(-4.125,1.75) 4(-4.125,1.25) 5(-4.125,0.75) 6(-4.125,0.25) 7(-4.125,-0.25) 8(-4.125,-0.75) 9(-4.125,-1.25) 10(-4.125,-1.75) 11(-4.125,-2.25) 12(-4.125,-2.75) 25(4.125,-2.75) 26(4.125,-2.25) 27(4.125,-1.75) 28(4.125,-1.25) 29(4.125,-0.75) 30(4.125,-0.25) 31(4.125,0.25) 32(4.125,0.75) 33(4.125,1.25) 34(4.125,1.75) 35(4.125,2.25) 36(4.125,2.75)
  rrect100% 0.3x1.25 smd: 13(-2.75,-4.125) 14(-2.25,-4.125) 15(-1.75,-4.125) 16(-1.25,-4.125) 17(-0.75,-4.125) 18(-0.25,-4.125) 19(0.25,-4.125) 20(0.75,-4.125) 21(1.25,-4.125) 22(1.75,-4.125) 23(2.25,-4.125) 24(2.75,-4.125) 37(2.75,4.125) 38(2.25,4.125) 39(1.75,4.125) 40(1.25,4.125) 41(0.75,4.125) 42(0.25,4.125) 43(-0.25,4.125) 44(-0.75,4.125) 45(-1.25,4.125) 46(-1.75,4.125) 47(-2.25,4.125) 48(-2.75,4.125)
  rrect2% 4.9x4.9 smd: 49(0,0)
  silkscreen extent -4.15,3.3 -3.9,3.55, body extent -4.51,-4.51 4.51,4.51, height 1.2
SDB06A [mm] "SON, 6-Leads, Body 2.2x2.5mm, Pitch 0.65mm, NSC Recommended (SC-70 Land)"
  rect 0.6x0.25 smd paste-0.125 mask+0.051: 1(-1.15,0.65) 2(-1.15,0) 3(-1.15,-0.65) 4(1.15,-0.65) 5(1.15,0) 6(1.15,0.65)
  rect 0.75x1.2 smd paste-0.6 mask+0.051: 7(0,0)
  silkscreen extent -2.28,-1.3 1.6,1.45, body extent -1.3,-1.15 1.3,1.15, height 0.8
SMA [mm] "Molded Diode, 2-Leads, Body 4.3x2.6mm, IPC Medium Density, based on OnSemi component dimensions and land pattern"
  rect 2x2 smd: 1(-2,0) 2(2,0)
  silkscreen extent -3.66,-1.57 2.79,1.57, body extent -2.6,-1.3 2.6,1.3, height 2.42
SOD-123 [mm] "On Semi recommended land pattern"
  rect 0.915x1.22 smd: 1(-1.637,0) 2(1.637,0)
  silkscreen extent -2.74,-1.17 2.03,1.17, body extent -1.93,-0.9 1.93,0.9, height 1.35
SOD-123F [mm] "NXP recommended land pattern"
  rect 1.2x1.2 smd paste-0.05: 1(-1.4,0) 2(1.4,0)
  silkscreen extent -2.64,-1.12 2.01,1.12, body extent -1.8,-0.85 1.8,0.85, height 1.2
SOD-123HE [mm] "SMD, 2-Leads, Body 2.8x1.8mm"
  rect 2.3x1.4 smd: 1(-0.9,0)
  rect 1.25x1.4 smd: 2(1.425,0)
  silkscreen extent -2.7,-1.1 2,1.1, body extent -1.5,-0.97 1.5,0.97, height 1
sod-323 [mm] "NXP recommended land pattern"
  rect 0.6x0.6 smd paste-0.05: 1(-1.1,0) 2(1.1,0)
  silkscreen extent -2.06,-0.86 1.53,0.86, body extent -1.3,-0.67 1.3,0.68, height 1.1
SOD-323 [mm] "NXP recommended land pattern"
  rect 0.6x0.6 smd paste-0.05: 1(-1.1,0) 2(1.1,0)
  silkscreen extent -2.06,-0.86 1.53,0.86, body extent -1.3,-0.67 1.3,0.68, height 1.1
SOD-523 [mm] "NXP Semiconductor recommended land pattern, nominal STEP model"
  rect 0.8x0.6 smd paste-0.05: 1(-0.55,0) 2(0.55,0)
  silkscreen extent -1.65,-0.66 1.2,0.66, body extent -0.8,-0.4 0.8,0.4, height 0.72
SOT-23 [mm] "SOT23, 3-Leads, Body 2.9x1.3mm, Pitch 0.95mm, Lead Span 2.5mm, IPC Medium Density"
  rrect50% 1x0.6 smd: 1(-1.2,0.95) 2(-1.2,-0.95) 3(1.2,0)
  silkscreen extent -1.63,-1.5 0.7,1.5, body extent -1.16,-1.45 1.21,1.45, height 1
SOT-323 [mm] "Diodes Inc recommended land pattern.  2016-02-24"
  rrect21% 0.6x0.47 smd: 1(-0.95,0.65) 2(-0.95,-0.65) 3(0.95,0)
  silkscreen extent -1.14,-1.22 0.77,1.22, body extent -1.13,-1.13 1.12,1.12, height 1.13
WL-SMCW_GREEN [mm] "WURTH"
  rect 0.8x0.8 smd: 1(-0.8,0) 2(0.8,0)
  silkscreen extent -1.9,-0.8 1.2,0.8, body extent -0.85,-0.45 0.85,0.45, height 0.8
WL-SMCW_YELLOW [mm] "WURTH"
  rect 0.8x0.8 smd: 1(-0.8,0) 2(0.8,0)
  silkscreen extent -1.9,-0.8 1.2,0.8, body extent -0.85,-0.45 0.85,0.45, height 0.8

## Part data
"A to B": "LED, Yellow, SMD", Color=yellow, Manufacturer="Wurth Elektronik", Supplier Part Number 1=732-4981-1-ND, Value1=W, Value2=2V
"B to A": "LED, Green, SMD", Color=green, Manufacturer="Wurth Elektronik", Supplier Part Number 1=732-4980-1-ND, Value1=W, Value2=2V
C1 C9 C25 C42 C44 C47 C55 C74 C76 C120: "CAP, CERM, 0.1 µF, 100 V, +/- 10%, X7R, 0603", Cap_Case=0603, Manufacturer=MuRata, Supplier Part Number 1=490-3285-1-ND, TempCo=X7R, Tolerance_%=10, Value1=Unknown, Value2=100V, ValueDisplayed=0.1µF
C2 C11: library part CMP-0006920-4, "CAP, CERM, 330 pF, 50 V, +/- 5%, C0G/NP0, 0603", Cap_Case=0603, Manufacturer=Kemet, Supplier Part Number 1=399-1068-1-ND, TempCo=C0G/NP0, Tolerance_%=5%, Value1=Unknown, Value2=50V, ValueDisplayed=330pF
C3 C10: library part CMP-0006811-4, "CAP, CERM, 10 pF, 10 V, +/- 10%, X7R, 0603", Cap_Case=0603, Manufacturer=AVX, Supplier Part Number 1=0603ZC100KAT2A-ND, TempCo=X7R, Tolerance_%=10%, Value1=Unknown, Value2=10V, ValueDisplayed=10pF
C4 C13: library part CMP-0007440-5, "CAP, CERM, 0.018 uF, 50 V, +/- 10%, X7R, 0603", Cap_Case=0603, Manufacturer=MuRata, Supplier Part Number 1=490-1516-1-ND, TempCo=X7R, Tolerance_%=10%, Value1=Unknown, Value2=50V, ValueDisplayed=0.018uF
C5 C12: library part CMP-0007453-4, "CAP, CERM, 3900 pF, 50 V, +/- 10%, X7R, 0603", Cap_Case=0603, Manufacturer=MuRata, Supplier Part Number 1=490-1504-1-ND, TempCo=X7R, Tolerance_%=10%, Value1=Unknown, Value2=50V, ValueDisplayed=3900pF
C6 C15: library part CMP-0007659-2, "CAP, CERM, 0.047 uF, 50 V, +/- 10%, X7R, 0805", Cap_Case=0805, Manufacturer=AVX, Supplier Part Number 1=478-1391-1-ND, TempCo=X7R, Tolerance_%=10%, Value1="0.035 ohm", Value2=50V, ValueDisplayed=0.047uF
C7 C14: library part CMP-0007694-2, "CAP, CERM, 0.01 uF, 50 V, +/- 10%, X7R, 0805", Cap_Case=0805, Manufacturer="Wurth Elektronik", Supplier Part Number 1=732-8074-1-ND, TempCo=X7R, Tolerance_%=10%, Value1=Unknown, Value2=50V, ValueDisplayed=0.01uF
